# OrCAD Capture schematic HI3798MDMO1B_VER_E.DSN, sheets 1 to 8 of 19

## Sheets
1 SHEET01
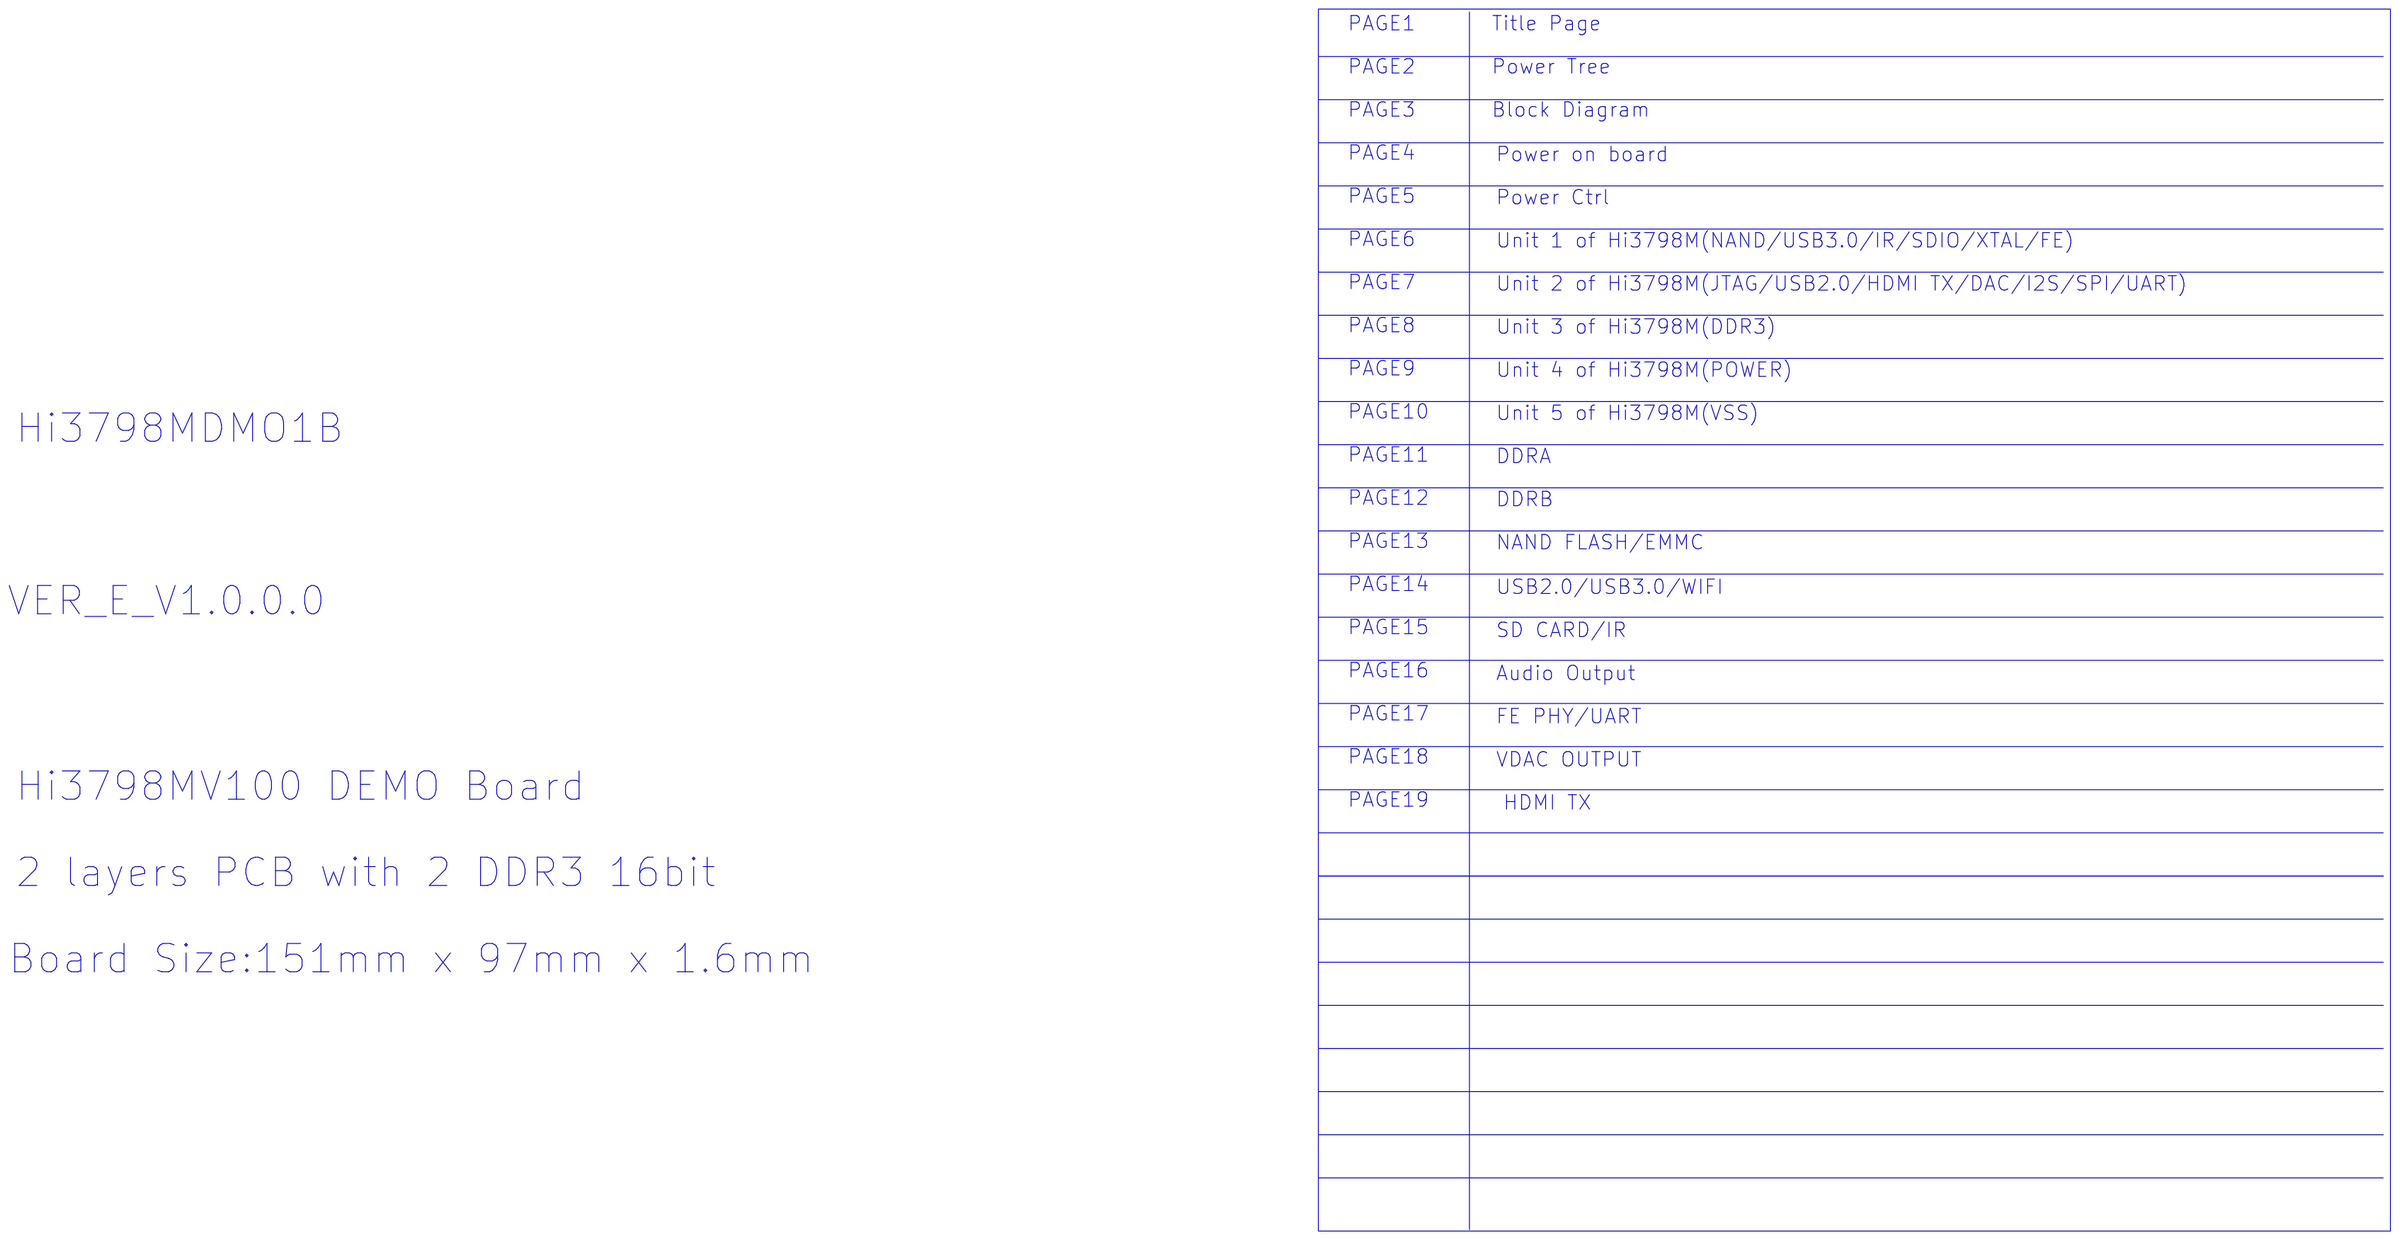
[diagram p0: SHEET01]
2 SHEET02
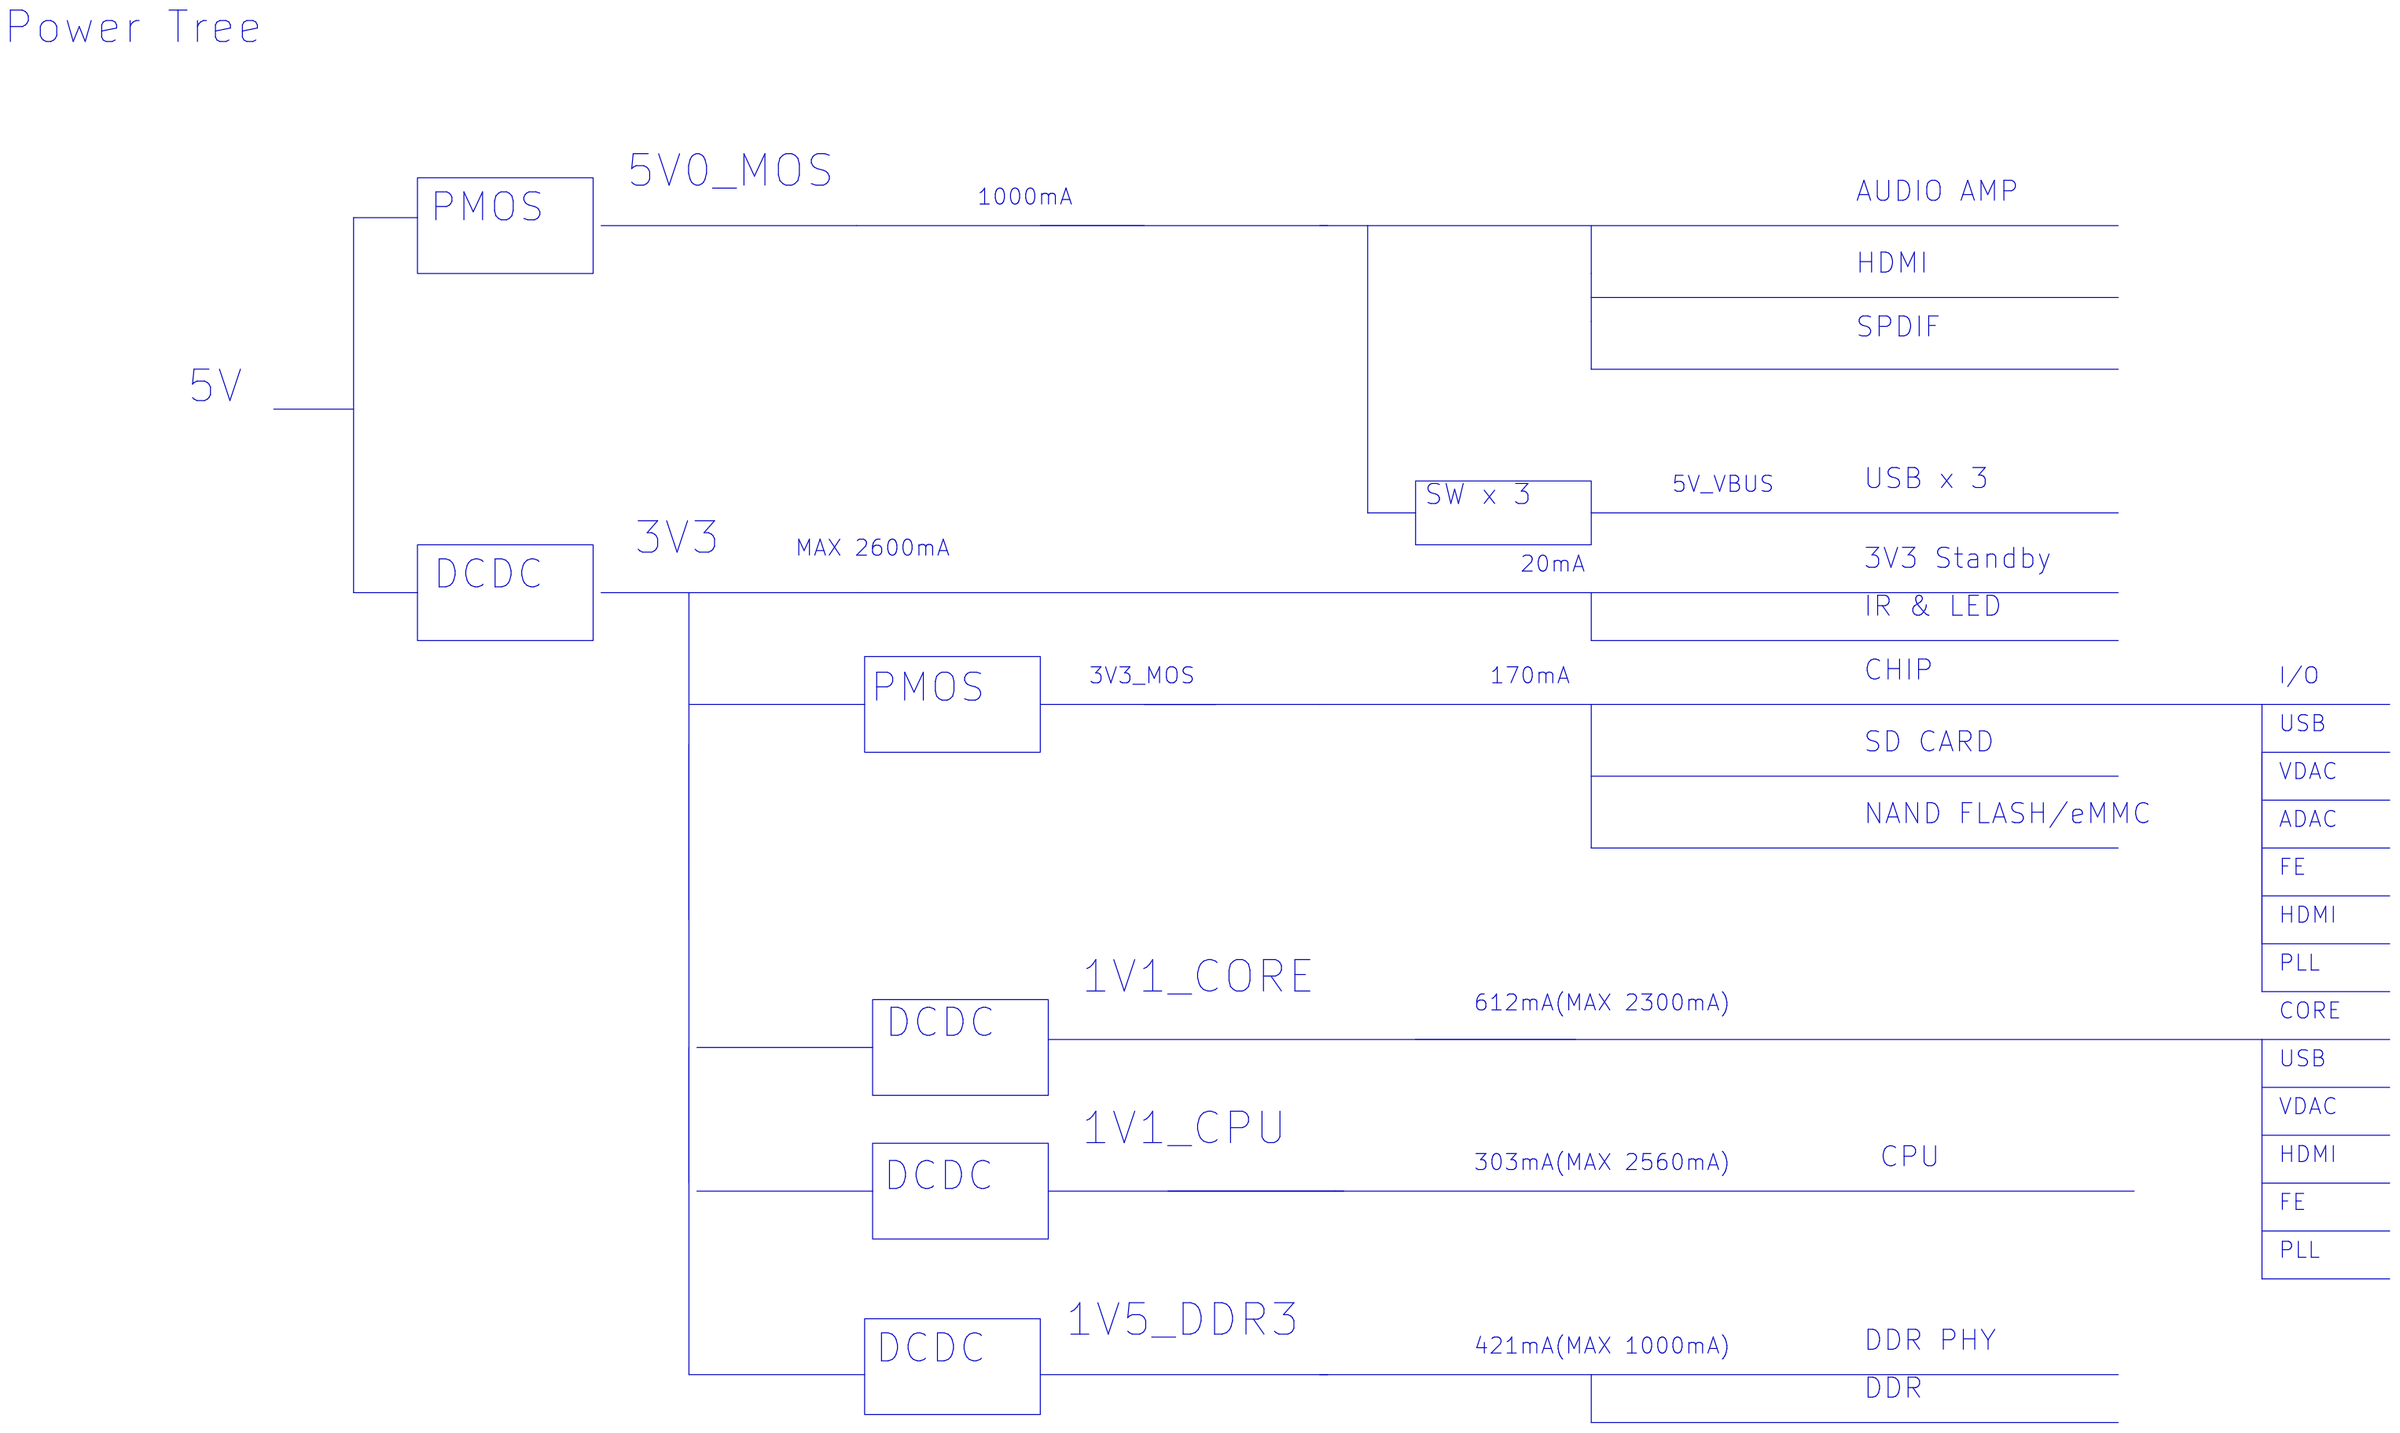
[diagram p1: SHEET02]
3 SHEET03: size Custom
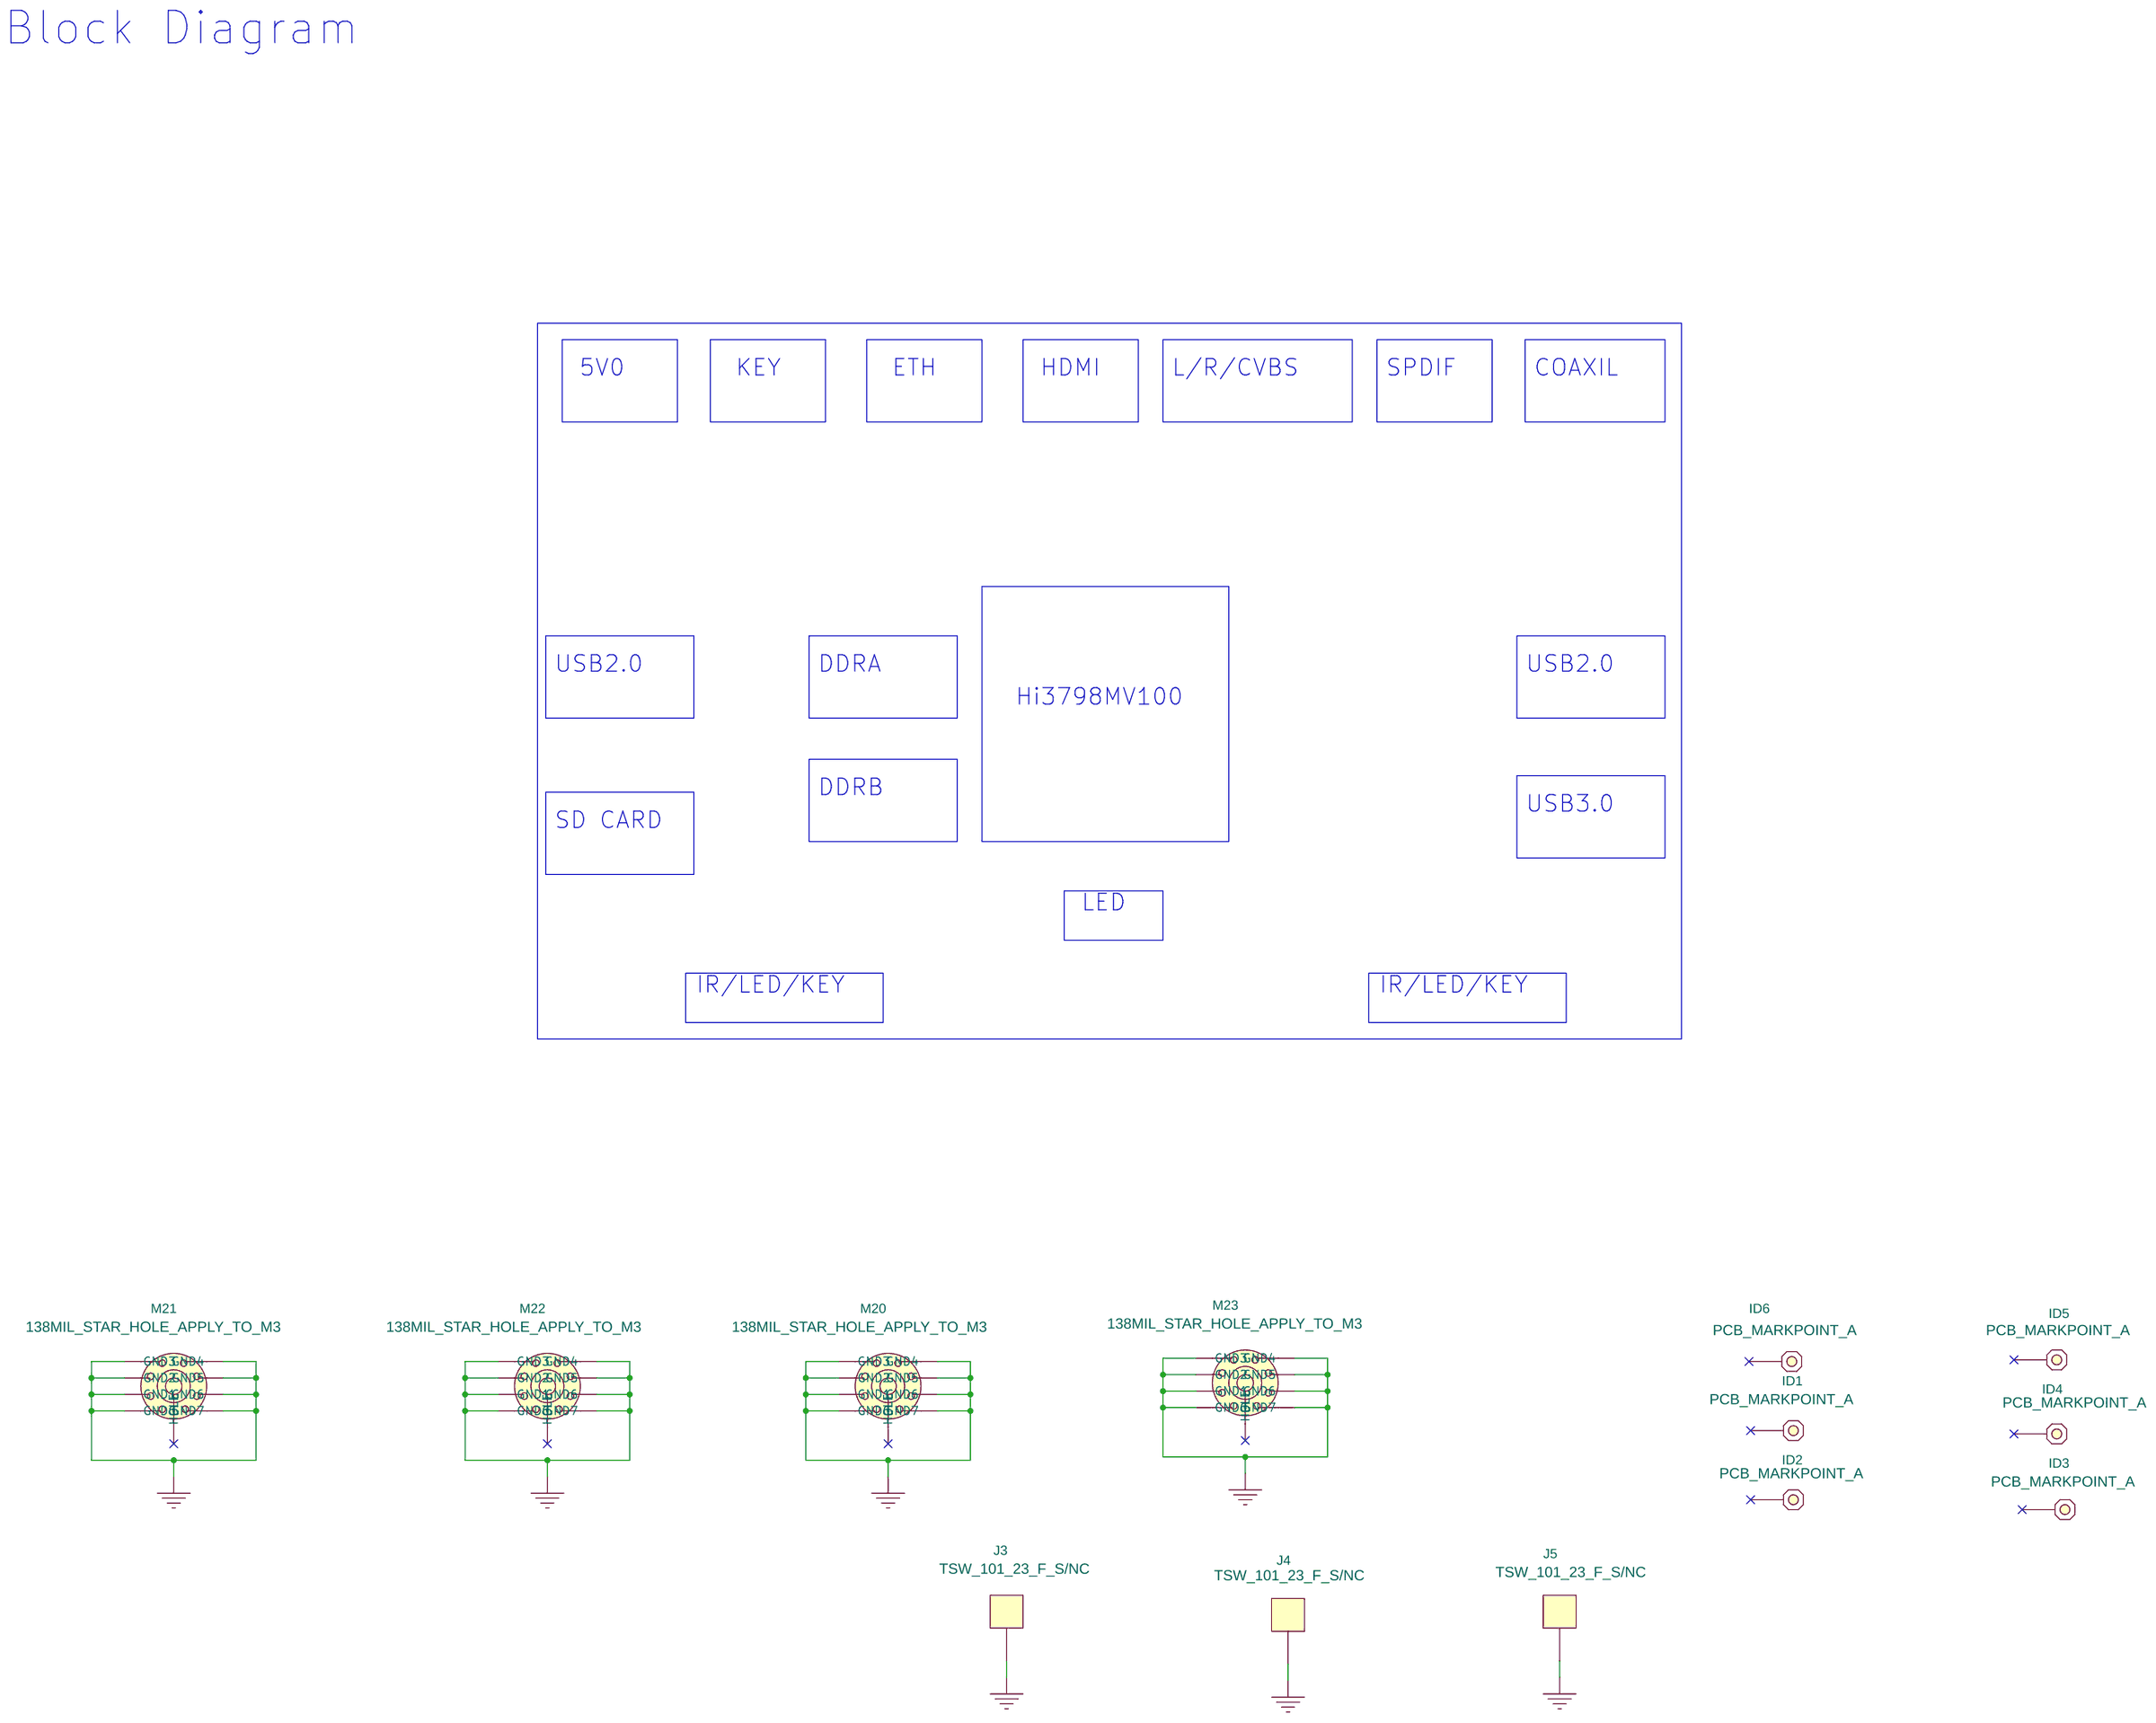
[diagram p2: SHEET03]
4 SHEET04: size Custom
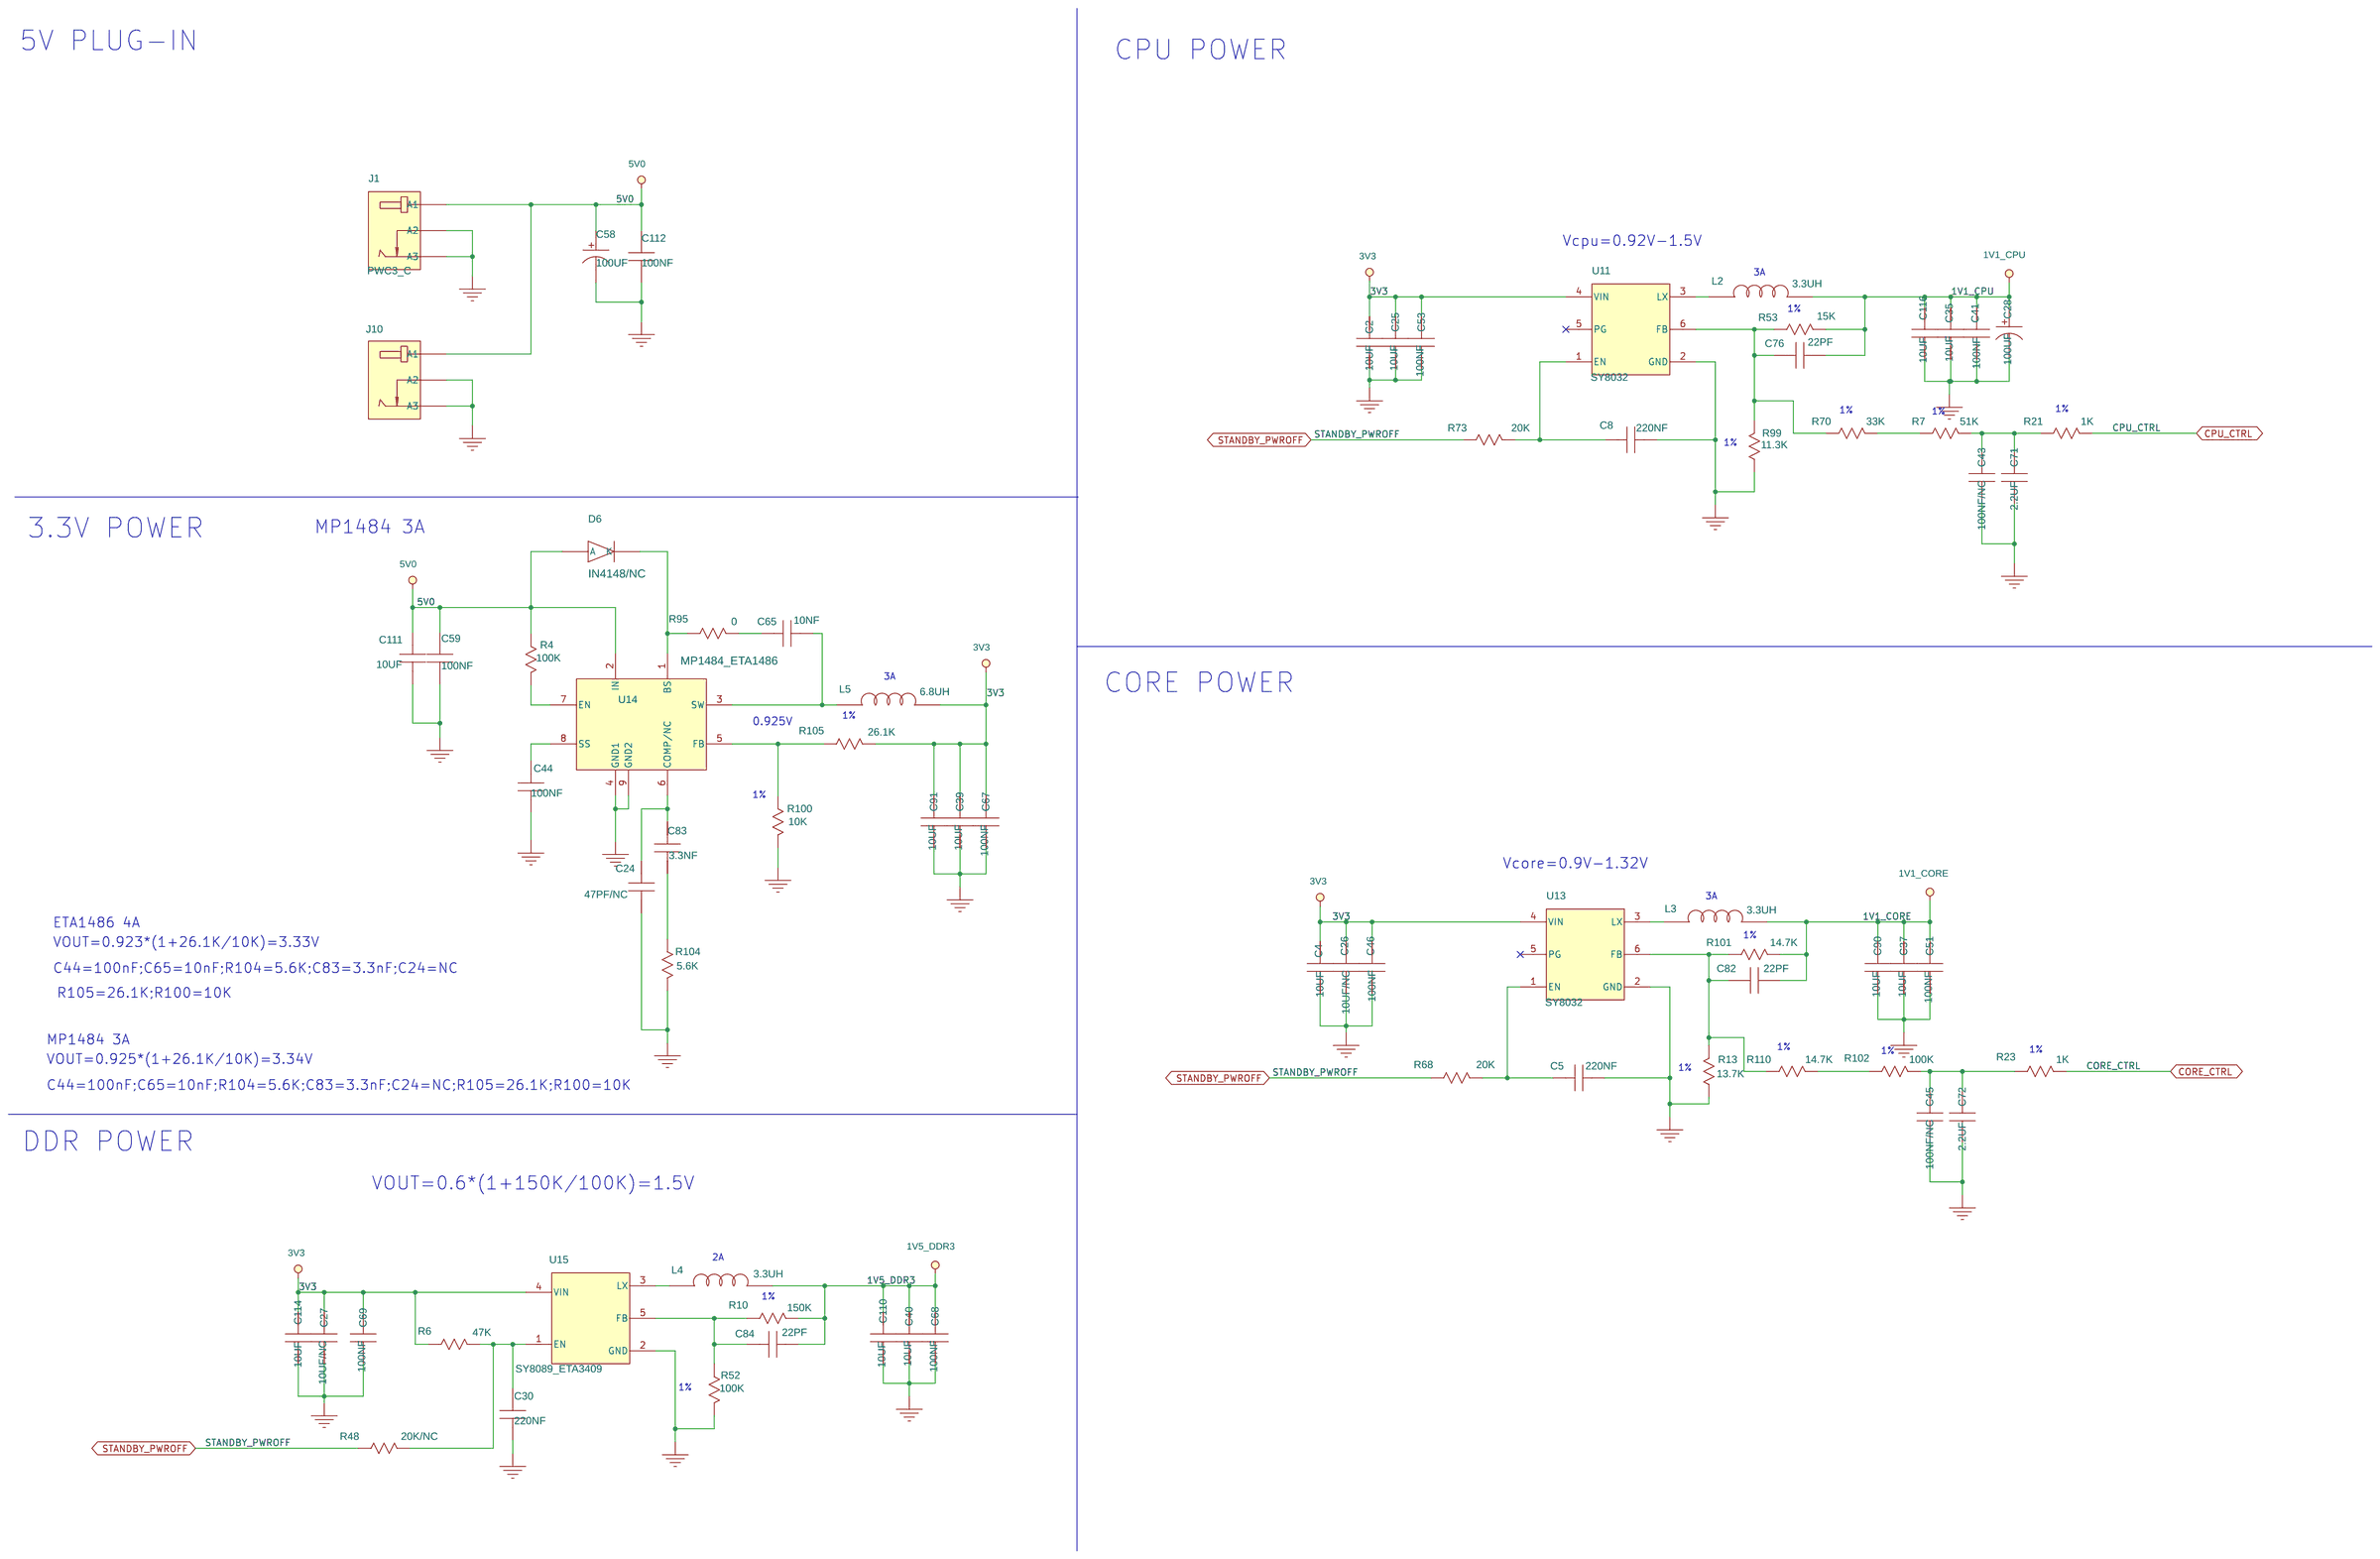
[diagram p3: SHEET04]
5 SHEET05: size A
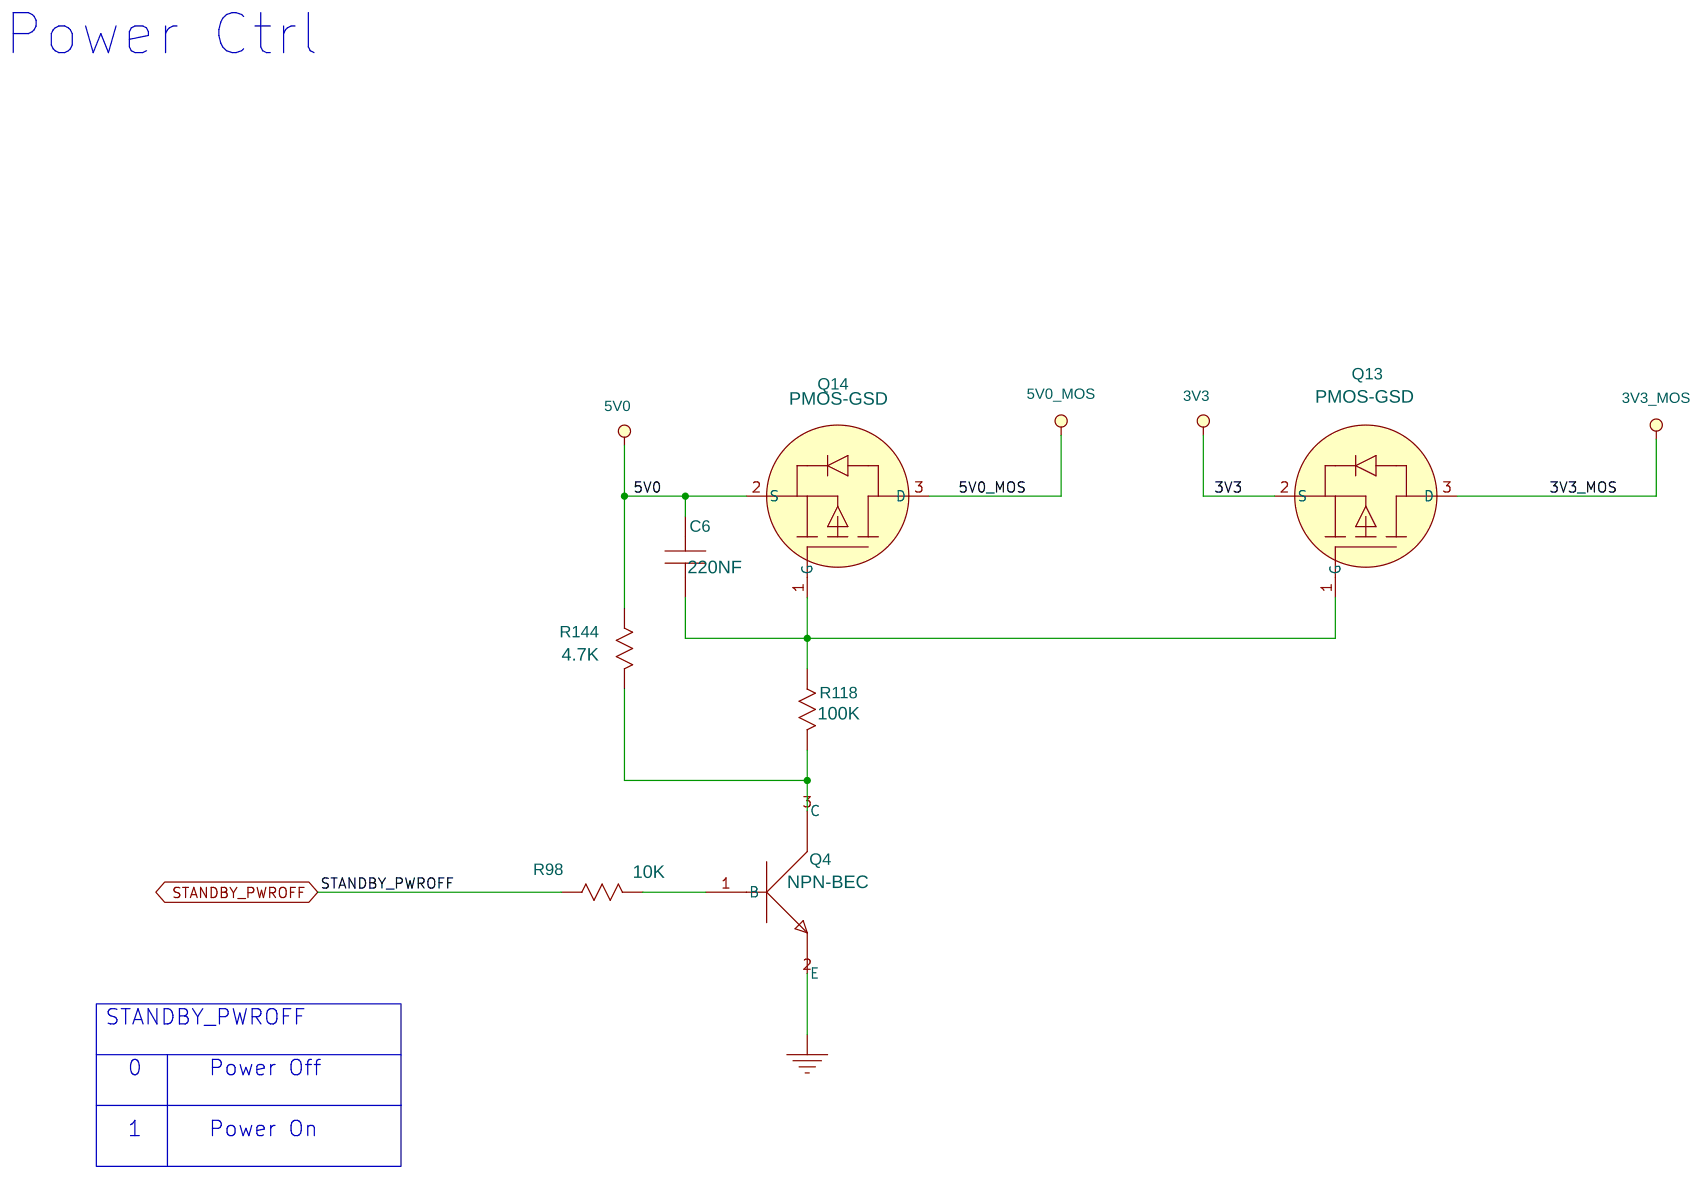
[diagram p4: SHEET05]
6 SHEET06: size Custom
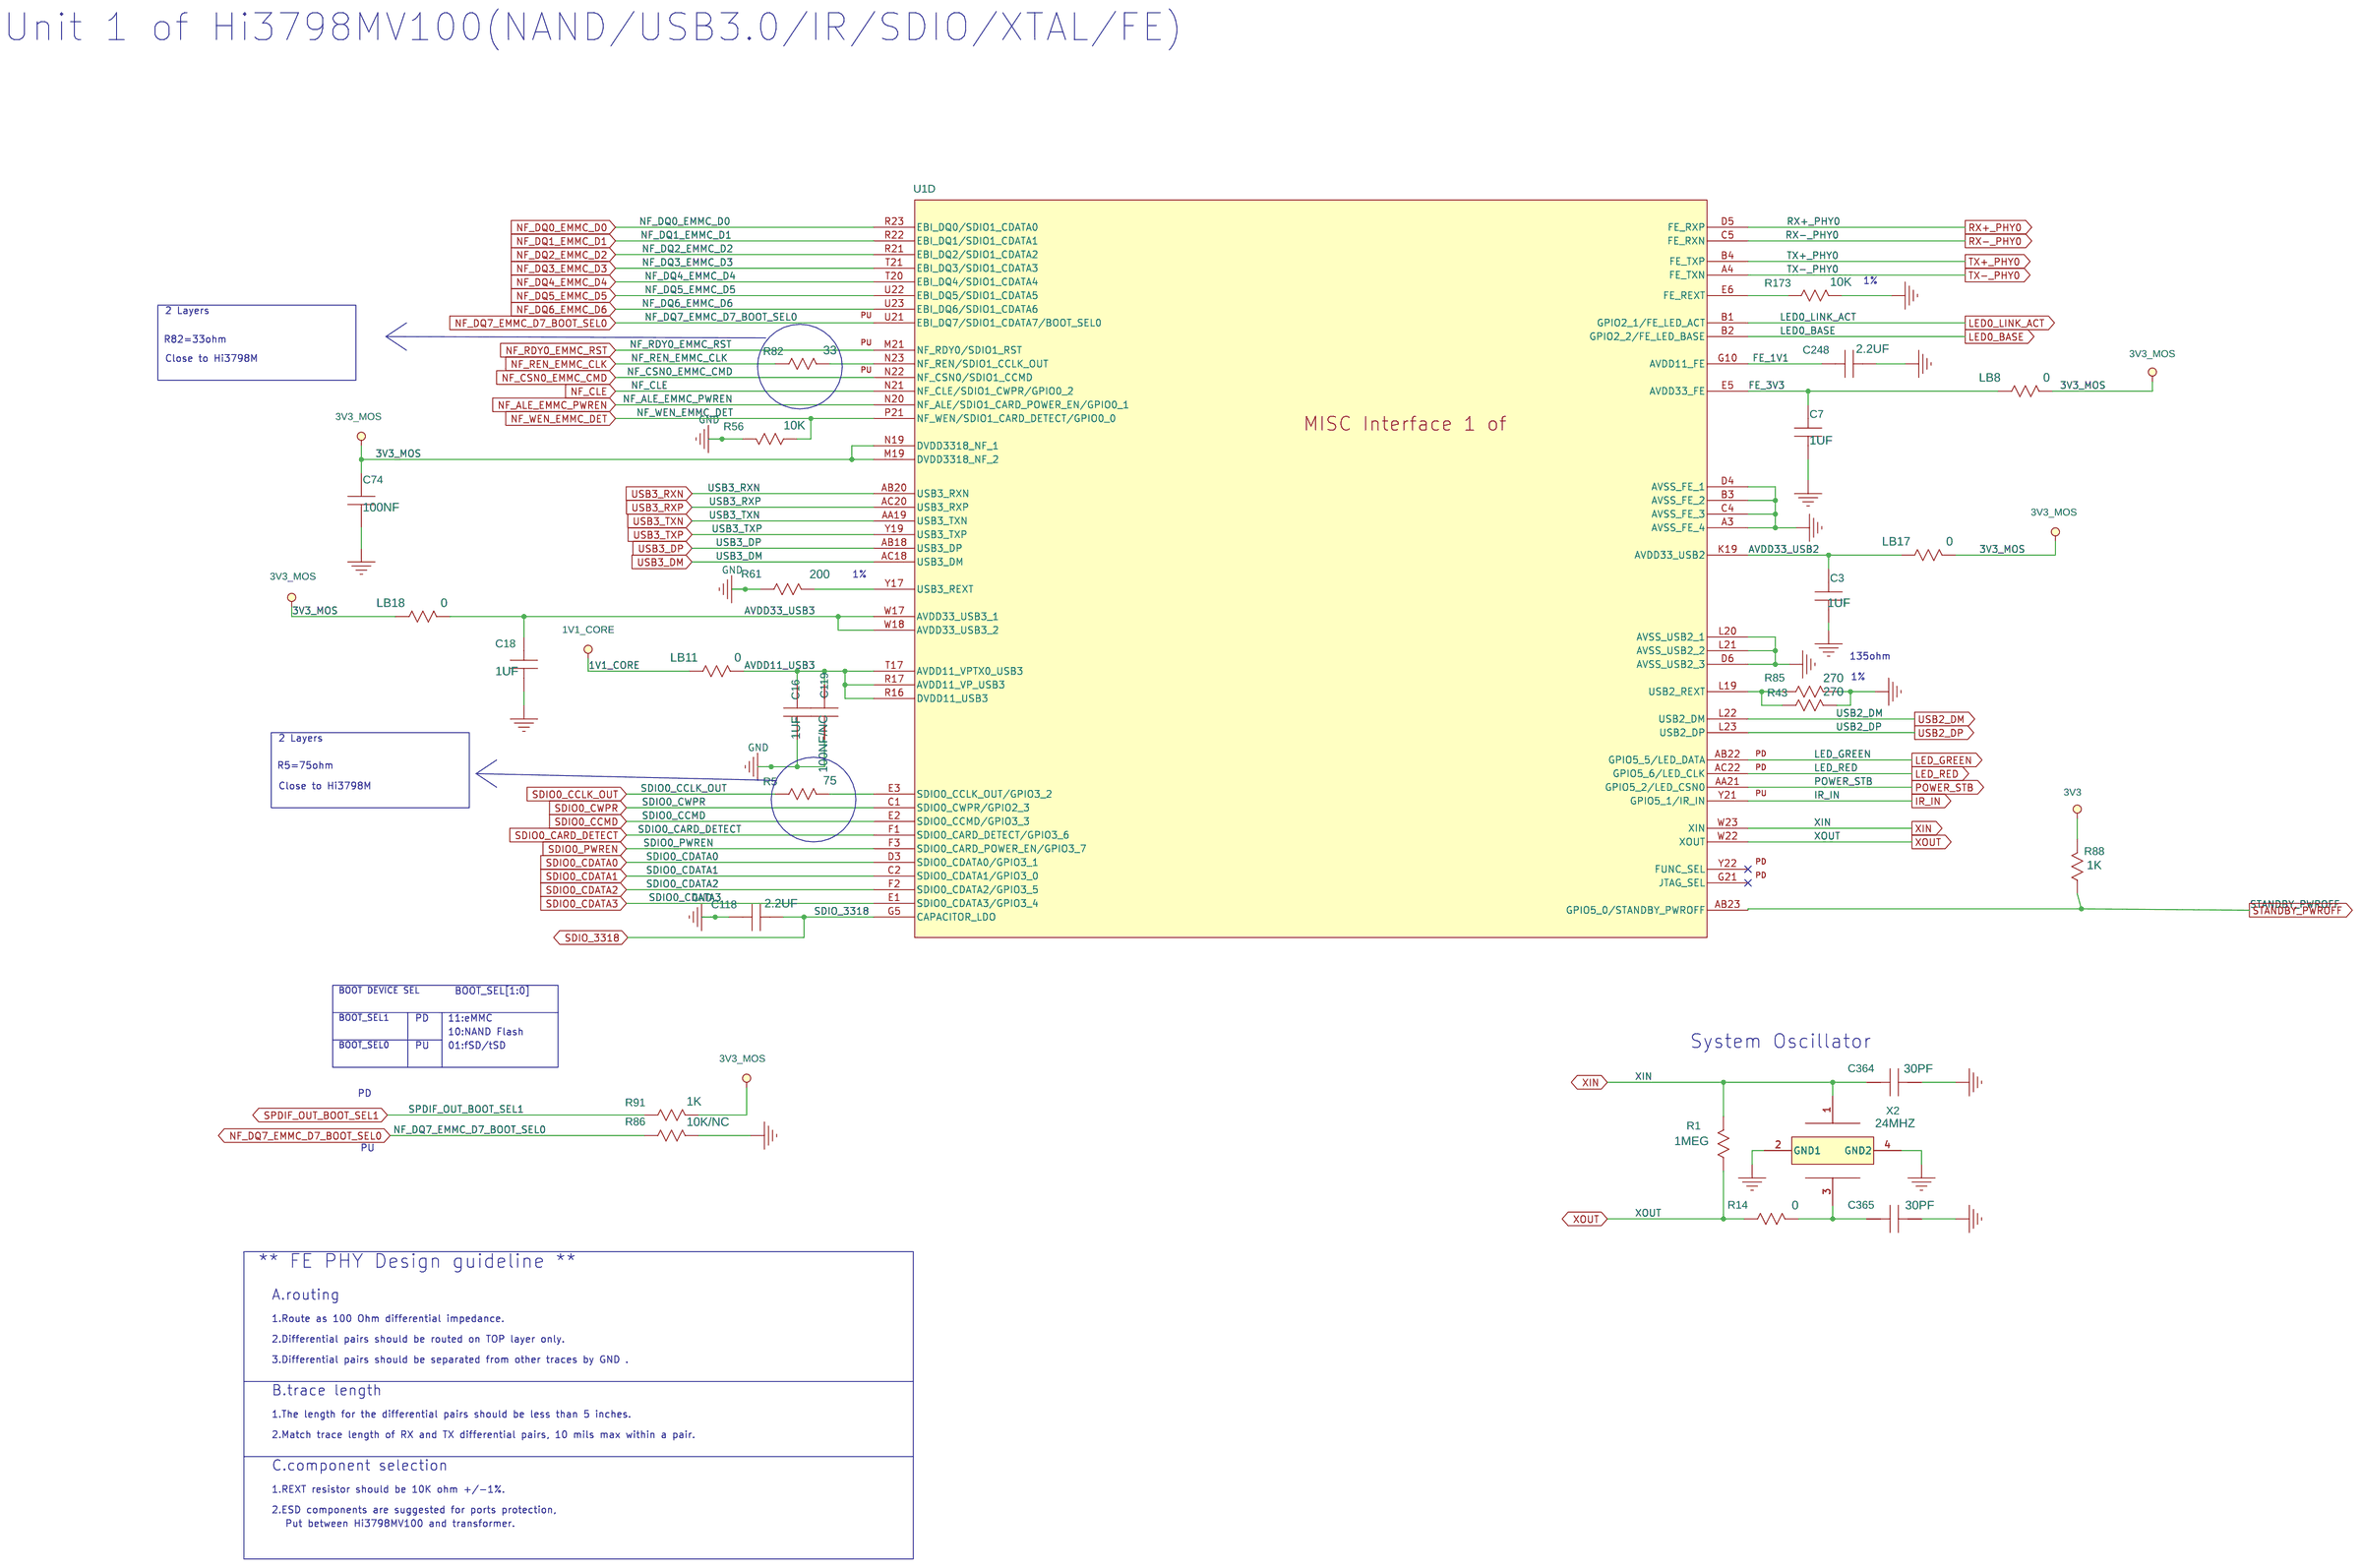
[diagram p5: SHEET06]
7 SHEET07: size Custom
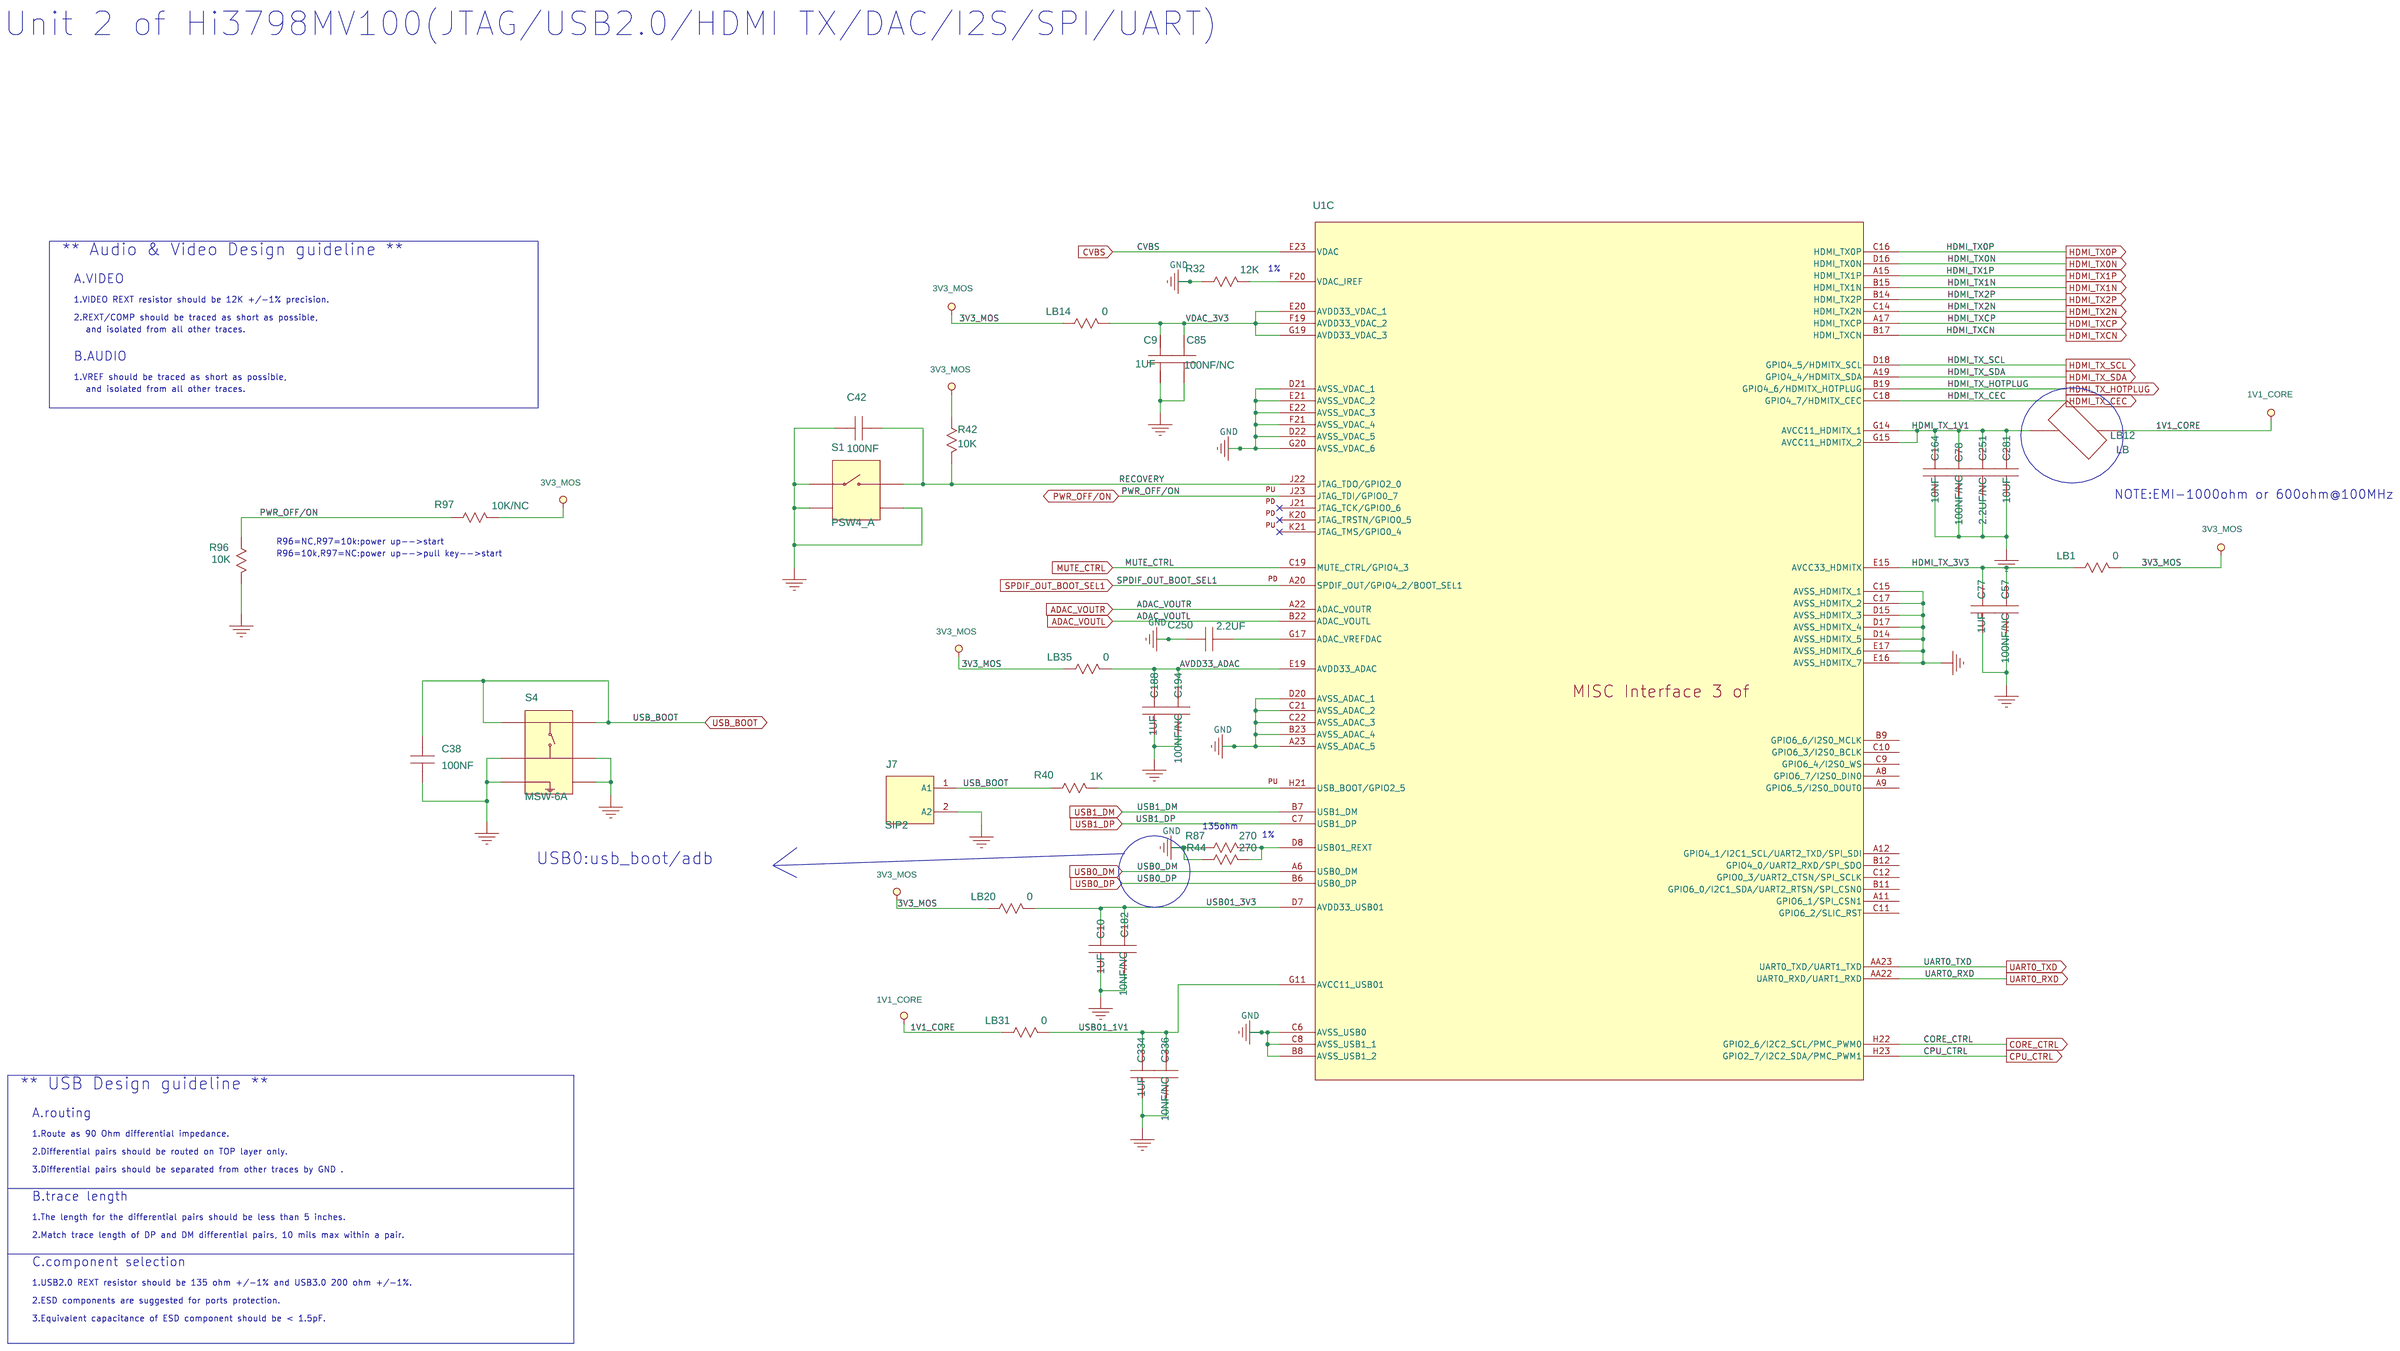
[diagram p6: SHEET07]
8 SHEET08: size Custom
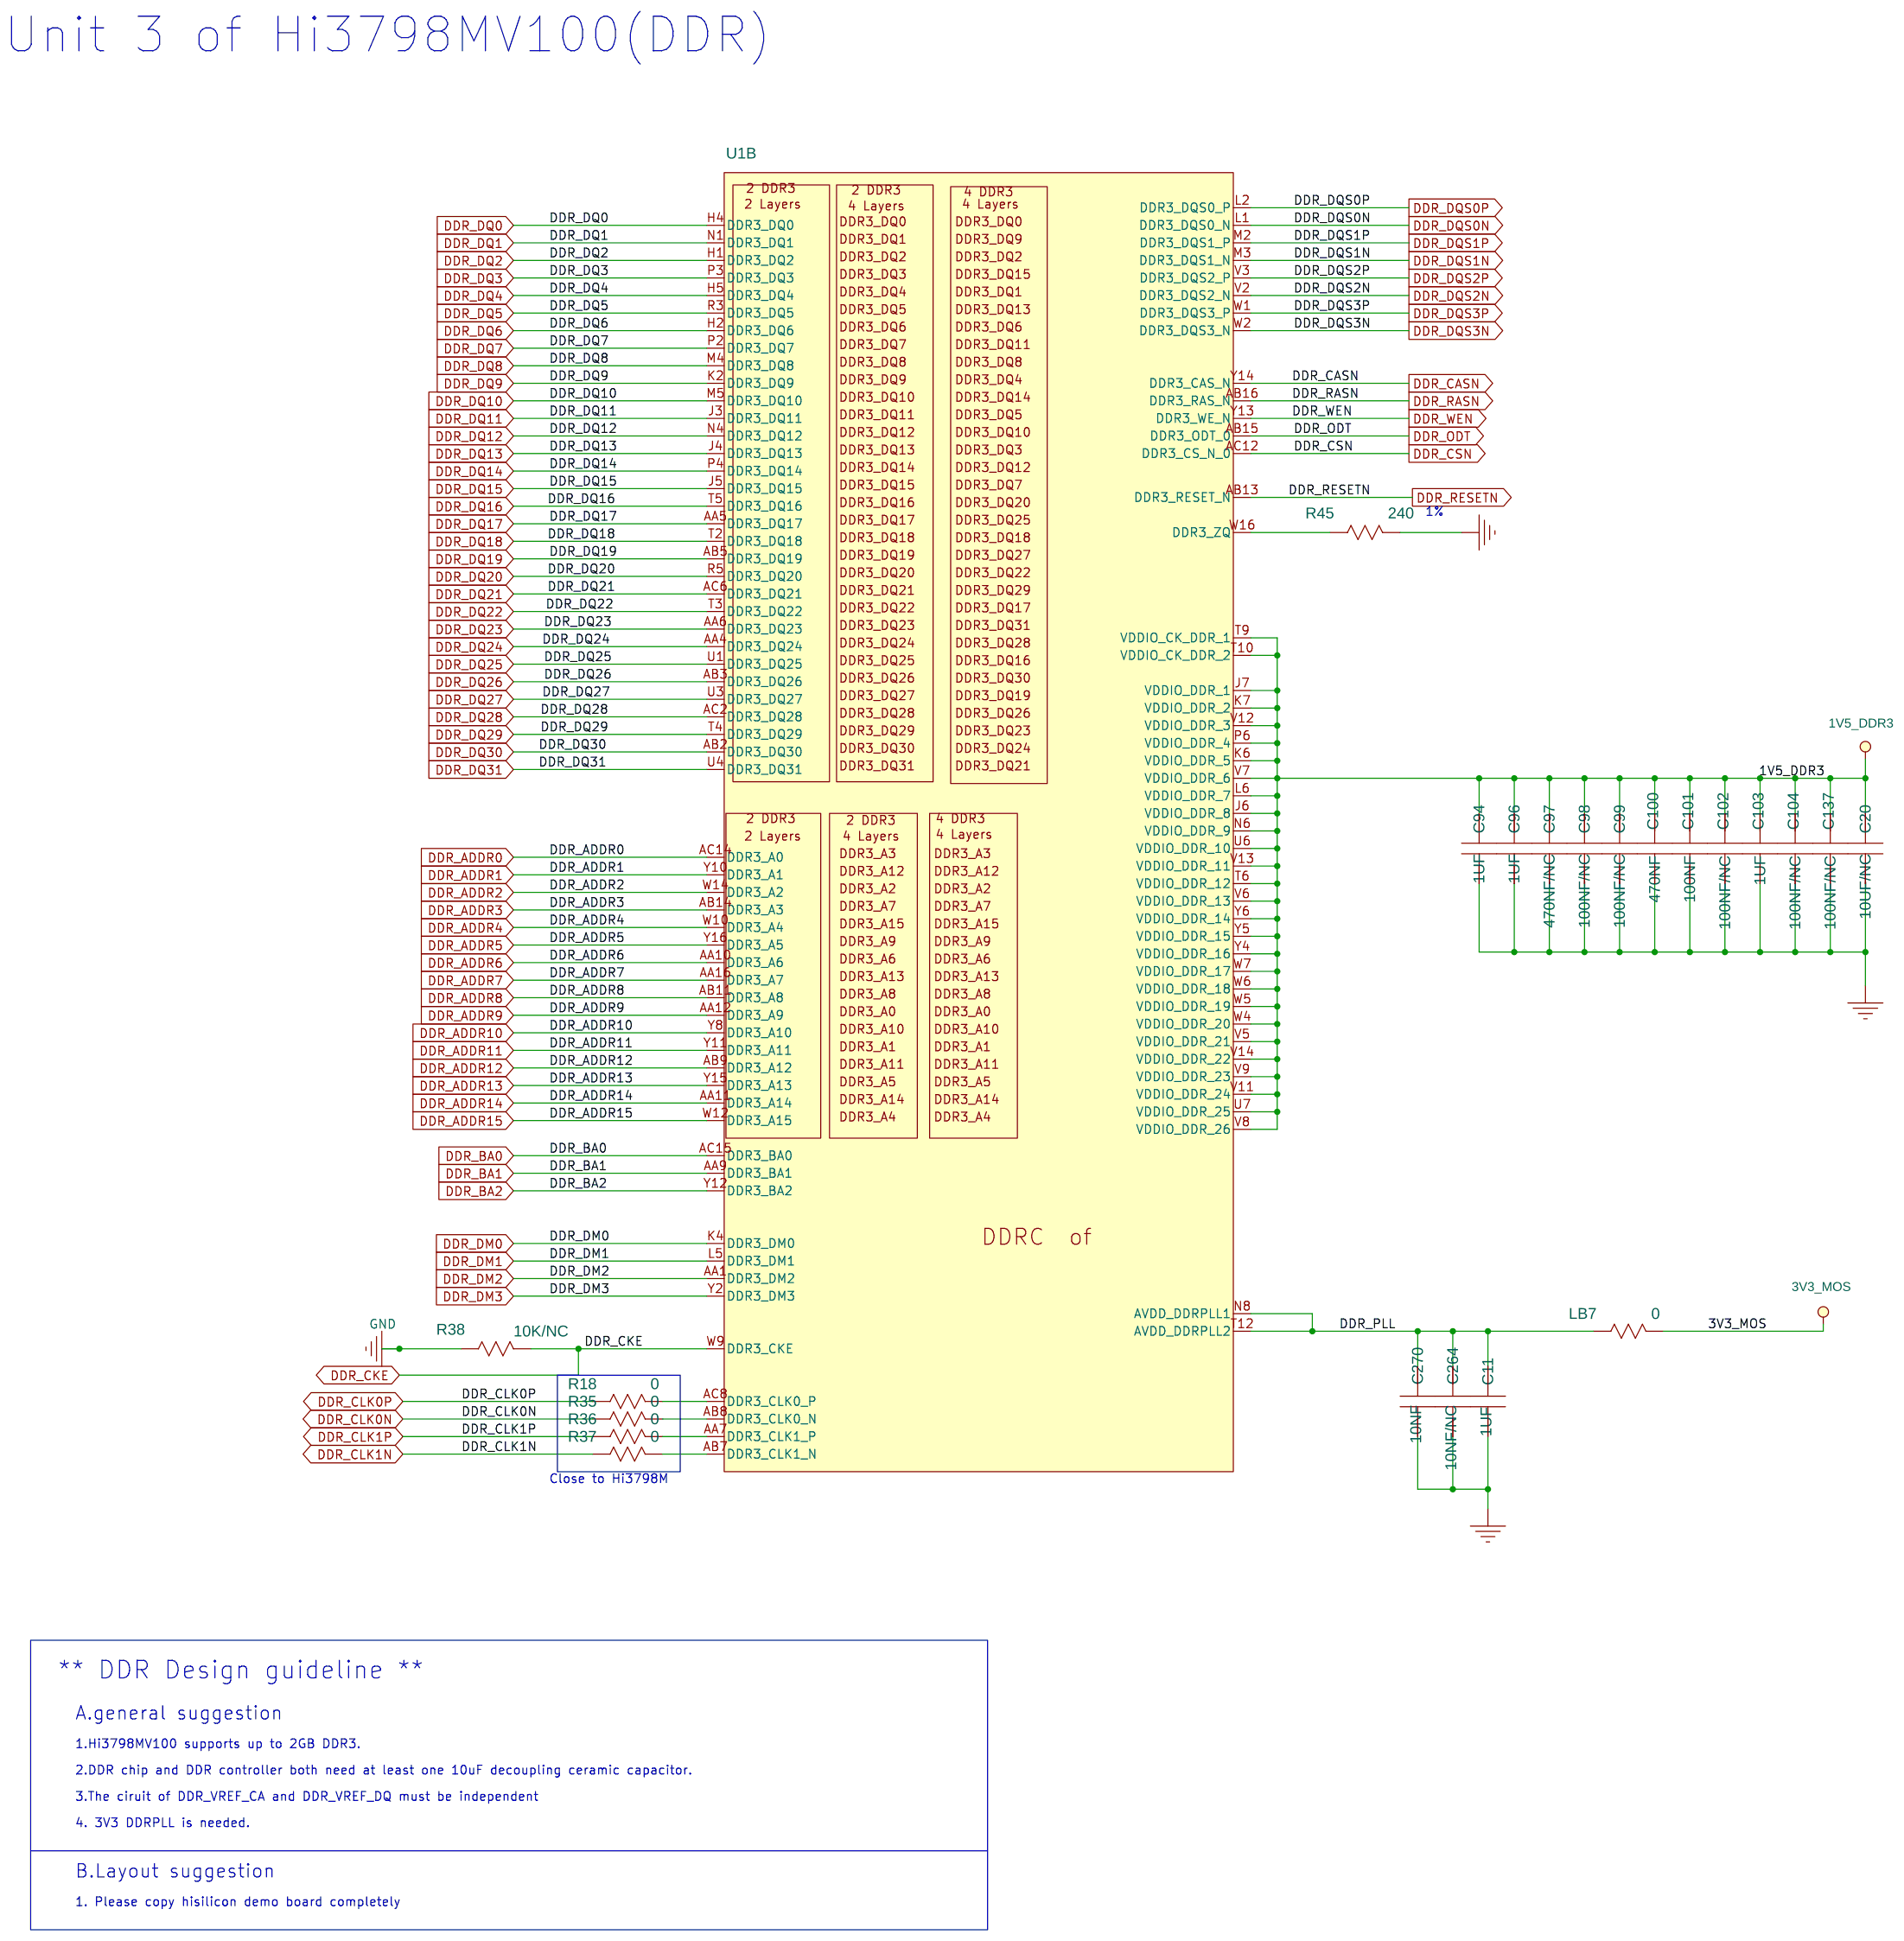
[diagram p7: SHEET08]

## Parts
sheet SHEET03
ID1  ID-BOARD  [ID-BOARD]
ID2  ID-BOARD  [ID-BOARD]
ID3  ID-BOARD  [ID-BOARD]
ID4  ID-BOARD  [ID-BOARD]
ID5  ID-BOARD  [ID-BOARD]
ID6  ID-BOARD  [ID-BOARD]
J3  SIP1  [SIP-1P]
J4  SIP1  [SIP-1P]
J5  SIP1  [SIP-1P]
M20  HOLE-8STARS  [HOLE138-8STAR]
M21  HOLE-8STARS  [HOLE138-8STAR]
M22  HOLE-8STARS  [HOLE138-8STAR]
M23  HOLE-8STARS  [HOLE138-8STAR]
sheet SHEET04
C2  10UF  [SC0805]
C4  10UF  [SC0805]
C5  220NF  [SC0402]
C8  220NF  [SC0402]
C24  47PF/NC  [SC0402]
C25  10UF  [SC0805]
C26  10UF/NC  [SC0805]
C27  10UF/NC  [SC0805]
C28  100UF  [SAC6666]
C30  220NF  [SC0402]
C35  10UF  [SC0603]
C37  10UF  [SC0603]
C39  10UF  [SC0603]
C40  10UF  [SC0603]
C41  100NF  [SC0402]
C43  100NF/NC  [SC0402]
C44  100NF  [SC0402]
C45  100NF/NC  [SC0402]
C46  100NF  [SC0402]
C51  100NF  [SC0402]
C53  100NF  [SC0402]
C58  100UF  [SAC6666]
C59  100NF  [SC0402]
C65  10NF  [SC0402]
C67  100NF  [SC0402]
C68  100NF  [SC0402]
C69  100NF  [SC0402]
C71  2.2UF  [SC0603]
C72  2.2UF  [SC0603]
C76  22PF  [SC0402]
C82  22PF  [SC0402]
C83  3.3NF  [SC0402]
C84  22PF  [SC0402]
C90  10UF  [SC0603]
C91  10UF  [SC0603]
C110  10UF  [SC0603]
C111  10UF  [SC0805]
C112  100NF  [SC0402]
C114  10UF  [SC0805]
C116  10UF  [SC0603]
D6  IN4148/NC  [HSOD323A]
J1  PWC3_C  [PWC3-RF-A]
J10  NC  [DC-002]
L2  3.3UH  [SWPA4020S]
L3  3.3UH  [SWPA4020S]
L4  3.3UH  [SWPA4020S]
L5  6.8UH  [SWPA5040S]
R4  100K  [SR0402]
R6  47K  [SR0402]
R7  51K  [SR0402]
R10  150K  [SR0402]
R13  13.7K  [SR0402]
R21  1K  [SR0402]
R23  1K  [SR0402]
R48  20K/NC  [SR0402]
R52  100K  [SR0402]
R53  15K  [SR0402]
R68  20K  [SR0402]
R70  33K  [SR0402]
R73  20K  [SR0402]
R95  0  [SR0402]
R99  11.3K  [SR0402]
R100  10K  [SR0402]
R101  14.7K  [SR0402]
R102  100K  [SR0402]
R104  5.6K  [SR0402]
R105  26.1K  [SR0402]
R110  14.7K  [SR0402]
U11  SY8032  [SOT23_6]
U13  SY8032  [SOT23_6]
U14  MP1484_ETA1486  [SOIC8N]
U15  SY8089_ETA3409  [SOT23_5]
sheet SHEET05
C6  220NF  [SC0603]
Q4  NPN-BEC  [SOT23]
Q13  PMOS-GSD  [SOT23]
Q14  PMOS-GSD  [SOT23]
R98  10K  [SR0402]
R118  100K  [SR0402]
R144  4.7K  [SR0402]
sheet SHEET06
C3  1UF  [SC0603]
C7  1UF  [SC0603]
C16  1UF  [SC0603]
C18  1UF  [SC0603]
C74  100NF  [SC0402]
C118  2.2UF  [HSC0402]
C119  100NF/NC  [SC0402]
C248  2.2UF  [HSC0402]
C364  30PF  [SC0402]
C365  30PF  [SC0402]
LB8  0  [SL0402]
LB11  0  [SL0402]
LB17  0  [SL0603]
LB18  0  [SL0402]
R1  1MEG  [SR0603]
R5  75  [SR0402]
R14  0  [SR0402]
R43  270  [SR0402]
R56  10K  [SR0402]
R61  200  [SR0402]
R82  33  [SR0402]
R85  270  [SR0402]
R86  10K/NC  [SR0402]
R88  1K  [SR0402]
R91  1K  [SR0402]
R173  10K  [SR0402]
X2  24MHZ  [X288]
sheet SHEET07
C9  1UF  [SC0603]
C10  1UF  [SC0603]
C38  100NF  [SC0402]
C42  100NF  [SC0402]
C57  100NF/NC  [SC0402]
C77  1UF  [SC0402]
C78  100NF/NC  [SC0402]
C85  100NF/NC  [SC0402]
C164  10NF  [SC0402]
C182  10NF/NC  [SC0402]
C188  1UF  [SC0603]
C194  100NF/NC  [SC0402]
C250  2.2UF  [HSC0402]
C251  2.2UF/NC  [SC0603]
C281  10UF  [SC0603]
C334  1UF  [SC0402]
C336  10NF/NC  [SC0402]
J7  SIP2  [SIP-2P]
LB1  0  [SL0402]
LB12  LB  [SL0402]
LB14  0  [SL0603]
LB20  0  [SL0402]
LB31  0  [SL0402]
LB35  0  [SL0402]
R32  12K  [SR0402]
R40  1K  [SR0402]
R42  10K  [SR0402]
R44  270  [SR0402]
R87  270  [SR0402]
R96  10K  [SR0402]
R97  10K/NC  [SR0402]
S1  PSW4_A  [TSW4-RG-C]
S4  MSW-6A  [SPSW6-T]
sheet SHEET08
C11  1UF  [SC0603]
C20  10UF/NC  [SC0805]
C94  1UF  [SC0402]
C96  1UF  [SC0402]
C97  470NF/NC  [SC0402]
C98  100NF/NC  [SC0402]
C99  100NF/NC  [SC0402]
C100  470NF  [SC0402]
C101  100NF  [SC0402]
C102  100NF/NC  [SC0402]
C103  1UF  [SC0402]
C104  100NF/NC  [SC0402]
C137  100NF/NC  [SC0402]
C264  10NF/NC  [SC0402]
C270  10NF  [SC0402]
LB7  0  [SL0603]
R18  0  [SR0402]
R35  0  [SR0402]
R36  0  [SR0402]
R37  0  [SR0402]
R38  10K/NC  [SR0402]
R45  240  [SR0402]
sheet SHEET09
U1  S40V300_19X19  [TFBGA395-32-2323]  (sections A,B,C,D,E)

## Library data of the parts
ID1-ID6 = ID-BOARD: %195%%232%%202%%246%: PCB-MARK点ID-BOARD，亮铜直径40MIL，阻焊开窗直径80MIL，MARK点大小120MIL。; DEVICE: PCB_MARKPOINT_A
J3-J5 = SIP1: %195%%232%%202%%246%: 插针-普通方脚插针-1PIN-单排-直式-5.84MM-2.92MM-2.54MM-THT; %208%%161%%192%%224%%195%%251%%179%%198%: 插针; CODE: 14050101; DEVICE: TSW_101_23_F_S/NC
M20-M23 = HOLE-8STARS: %195%%232%%202%%246%: M3螺钉(推荐使用)，对应138MIL星月孔，适用于过波峰焊设计。; DEVICE: 138MIL_STAR_HOLE_APPLY_TO_M3
C2 C4 C25-C27 C111 C114 = C: %182%%238%%182%%168%%185%%164%%215%%247%%181%%231%%209%%185%(V): 25; %195%%232%%202%%246%: SMD陶瓷电容-25V-10000NF-+/-20%-X5R-0805; %208%%161%%192%%224%%195%%251%%179%%198%: SMD陶瓷电容; CODE: 8071629; COMPONENT_HIGH_MAX: 1.45MM; DEVICE: C2012X5R1E106KT000N1
C5 C8 C30 = C: %182%%238%%182%%168%%185%%164%%215%%247%%181%%231%%209%%185%(V): 6.3; %195%%232%%202%%246%: SMD陶瓷电容-6.3V-220NF-+/-10%-X5R-0402-BT; %208%%161%%192%%224%%195%%251%%179%%198%: SMD陶瓷电容; CODE: 8070584; COMPONENT_HIGH_MAX: 0.55MM; DEVICE: GRM155R60J224KE01D
C24 = C: %182%%238%%182%%168%%185%%164%%215%%247%%181%%231%%209%%185%(V): 50; %195%%232%%202%%246%: SMD陶瓷电容-50V-0.047NF-±5%-NP0-0402; %208%%161%%192%%224%%195%%251%%179%%198%: SMD陶瓷电容; CODE: 8070549; COMPONENT_HIGH_MAX: 0.55MM; DEVICE: C0402C470J5GAC_7867
C28 C58 = CP: %182%%238%%182%%168%%185%%164%%215%%247%%181%%231%%209%%185%(V): 16; %195%%232%%202%%246%: 非固体SMD铝电容-16V-100UF-+/-20%-6.3*5.4MM-极性-105DEGC-1000H-片式,温度敏感器件-工艺耐温250DEGC,5S; %208%%161%%192%%224%%195%%251%%179%%198%: 非固体SMD铝电容; CODE: 8010269; COMPONENT_HIGH_MAX: 5.7MM; DEVICE: UWT1C101MCL1GB
C35 C37 C39 C40 C90 C91 C110 C116 C281 = C: %182%%238%%182%%168%%185%%164%%215%%247%%181%%231%%209%%185%(V): 6.3; %195%%232%%202%%246%: SMD陶瓷电容-6.3V-10000NF-+/-20%-X5R-0603-BT,TS16949; %208%%161%%192%%224%%195%%251%%179%%198%: SMD陶瓷电容; CODE: 8070649; COMPONENT_HIGH_MAX: 0.9MM; DEVICE: C1608X5R0J106MT0A0E
C41 C43 C45 C46 C51 C53 C59 C67-C69 C112 = C: %182%%238%%182%%168%%185%%164%%215%%247%%181%%231%%209%%185%(V): 16; %195%%232%%202%%246%: SMD陶瓷电容-16V-100NF-±10%-X7R-0402; %208%%161%%192%%224%%195%%251%%179%%198%: SMD陶瓷电容; CODE: 8070614; COMPONENT_HIGH_MAX: 0.6MM; DEVICE: RMEMK105BJ104KV_FR
C44 = C: %182%%238%%182%%168%%185%%164%%215%%247%%181%%231%%209%%185%(V): 16; %195%%232%%202%%246%: SMD陶瓷电容-16V-10NF-+/-10%-X7R-0402; %208%%161%%192%%224%%195%%251%%179%%198%: SMD陶瓷电容; CODE: 8070449; COMPONENT_HIGH_MAX: 0.55MM; DEVICE: GRM155R71C103KA01D
C65 = C: %182%%238%%182%%168%%185%%164%%215%%247%%181%%231%%209%%185%(V): 10; %195%%232%%202%%246%: SMD陶瓷电容-10V-33NF-+/-10%-X7R-0402; %208%%161%%192%%224%%195%%251%%179%%198%: SMD陶瓷电容; CODE: 8070598; COMPONENT_HIGH_MAX: 0.55MM; DEVICE: C1005X7R1C333KT000F
C71 C72 C251 = C: %182%%238%%182%%168%%185%%164%%215%%247%%181%%231%%209%%185%(V): 10; %195%%232%%202%%246%: SMD陶瓷电容-10V-2200NF-+/-10%-X5R-0603; %208%%161%%192%%224%%195%%251%%179%%198%: SMD陶瓷电容; CODE: 8070573; COMPONENT_HIGH_MAX: 0.9MM; DEVICE: GRM188R61A225KE34D
C76 C82 C84 = C: %182%%238%%182%%168%%185%%164%%215%%247%%181%%231%%209%%185%(V): 50; %195%%232%%202%%246%: SMD陶瓷电容-50V-0.022NF-+/-5%-NP0-0402-BT; %208%%161%%192%%224%%195%%251%%179%%198%: SMD陶瓷电容; CODE: 8070545; COMPONENT_HIGH_MAX: 0.55MM; DEVICE: RMUMK105CG220JV_F
C83 = C: %182%%238%%182%%168%%185%%164%%215%%247%%181%%231%%209%%185%(V): 50; %195%%232%%202%%246%: SMD陶瓷电容-50V-3.3NF-±10%-X7R-0402; %208%%161%%192%%224%%195%%251%%179%%198%: SMD陶瓷电容; CODE: 8070621; COMPONENT_HIGH_MAX: 0.55MM; DEVICE: GRM155R71H332KA01D
D6 = D_A: %195%%232%%202%%246%: 肖特基二极管-10V-3A-0.24V-SOD323-BT; %208%%161%%192%%224%%195%%251%%179%%198%: 肖特基二极管; CODE: 15010252; COMPONENT_HIGH_MAX: 1.1MM; DEVICE: BAT60BE6327
J1 = PWC3_C: %195%%232%%202%%246%: IO连接器-DC JACK-3PIN-母座-3.9/1.3MM弯式-5V2A-00482858; CODE: 14240410; COMPONENT_HIGH_MAX: 11.25MM; DEVICE: DC_012_HW
J10 = PWC3_C: %195%%232%%202%%246%: IO连接器-DC JACK-3PIN-母座-3.9/1.3MM弯式-5V2A-00482858; CODE: *; COMPONENT_HIGH_MAX: 11.25MM; DEVICE: DC_012_HW
L2-L4 = SWPA4020S3R3MT
L5 = SWPA5040S6R8MT
R4 = R: %182%%238%%182%%168%%185%%166%%194%%202%(W): 0.06; %195%%232%%202%%246%: 片式厚膜电阻器-0.0625W-100000OHM-+/-5%-0402; %208%%161%%192%%224%%195%%251%%179%%198%: 片式厚膜电阻器; %215%%232%%214%%181%%212%%202%%208%%237%%198%%171%%178%%238%: +/-5%; CODE: 7090831; COMPONENT_HIGH_MAX: 0.4MM; DEVICE: RK73B1ELTP104J
R6 = R: %182%%238%%182%%168%%185%%166%%194%%202%(W): 0.06; %195%%232%%202%%246%: 片式厚膜电阻器-0.0625W-47000OHM-+/-5%-0402-ELOM; %208%%161%%192%%224%%195%%251%%179%%198%: 片式厚膜电阻器; %215%%232%%214%%181%%212%%202%%208%%237%%198%%171%%178%%238%: +/-5%; CODE: 7090819; COMPONENT_HIGH_MAX: 0.4MM; DEVICE: RC0402JR_0747K
R7 R105 = R: %182%%238%%182%%168%%185%%166%%194%%202%(W): 0.06; %195%%232%%202%%246%: 片式厚膜电阻器-0.0625W-51000OHM-+/-1%-0402; %208%%161%%192%%224%%195%%251%%179%%198%: 片式厚膜电阻器; %215%%232%%214%%181%%212%%202%%208%%237%%198%%171%%178%%238%: +/-1%; CODE: 7091384; COMPONENT_HIGH_MAX: 0.4MM; DEVICE: RC_02W5102FT
R10 = R: %182%%238%%182%%168%%185%%166%%194%%202%(W): 0.06; %195%%232%%202%%246%: 片式厚膜电阻器-0.0625W-150000OHM-+/-1%-0402; %208%%161%%192%%224%%195%%251%%179%%198%: 片式厚膜电阻器; %215%%232%%214%%181%%212%%202%%208%%237%%198%%171%%178%%238%: +/-1%; CODE: 7090833; COMPONENT_HIGH_MAX: 0.4MM; DEVICE: RK73H1ELTP1503F
R13 = R: %182%%238%%182%%168%%185%%166%%194%%202%(W): 0.1; %195%%232%%202%%246%: 片式厚膜电阻器-0.1W-26100OHM-+/-1%-0603-BT; %208%%161%%192%%224%%195%%251%%179%%198%: 片式厚膜电阻器; %215%%232%%214%%181%%212%%202%%208%%237%%198%%171%%178%%238%: +/-1%; CODE: 7091991; COMPONENT_HIGH_MAX: 0.55MM; DEVICE: RK73H1JTTD2612F
R21 R23 = R: %182%%238%%182%%168%%185%%166%%194%%202%(W): 0.1; %195%%232%%202%%246%: 片式厚膜电阻器-0.1W-1000OHM-+/-1%-0603; %208%%161%%192%%224%%195%%251%%179%%198%: 片式厚膜电阻器; %215%%232%%214%%181%%212%%202%%208%%237%%198%%171%%178%%238%: +/-1%; CODE: 7092250; COMPONENT_HIGH_MAX: 0.5MM; DEVICE: RK73H1JTTD1001F
R48 R68 R73 = R: %182%%238%%182%%168%%185%%166%%194%%202%(W): 0.06; %195%%232%%202%%246%: 片式厚膜电阻器-0.0625W-20000OHM-+/-1%-0402-TS16949; %208%%161%%192%%224%%195%%251%%179%%198%: 片式厚膜电阻器; %215%%232%%214%%181%%212%%202%%208%%237%%198%%171%%178%%238%: +/-1%; CODE: 7091374; COMPONENT_HIGH_MAX: 0.65MM; DEVICE: RC_02W2002FT
R52 R118 = R: %182%%238%%182%%168%%185%%166%%194%%202%(W): 0.06; %195%%232%%202%%246%: 片式厚膜电阻器-0.0625W-100000OHM-+/-5%-0402-BT; %208%%161%%192%%224%%195%%251%%179%%198%: 片式厚膜电阻器; %215%%232%%214%%181%%212%%202%%208%%237%%198%%171%%178%%238%: +/-5%; CODE: 7090831; COMPONENT_HIGH_MAX: 0.4MM; DEVICE: RK73B1ELTP104J
R53 R100 = R: %182%%238%%182%%168%%185%%166%%194%%202%(W): 0.06; %195%%232%%202%%246%: 片式厚膜电阻器-0.0625W-15000OHM-+/-1%-0402-BT; %208%%161%%192%%224%%195%%251%%179%%198%: 片式厚膜电阻器; %215%%232%%214%%181%%212%%202%%208%%237%%198%%171%%178%%238%: +/-1%; CODE: 7091372; COMPONENT_HIGH_MAX: 0.4MM; DEVICE: RC_02W1502FT
R70 = R: %182%%238%%182%%168%%185%%166%%194%%202%(W): 0.06; %195%%232%%202%%246%: 片式厚膜电阻器-0.0625W-33000OHM-+/-5%-0402; %208%%161%%192%%224%%195%%251%%179%%198%: 片式厚膜电阻器; %215%%232%%214%%181%%212%%202%%208%%237%%198%%171%%178%%238%: +/-5%; CODE: 7090828; COMPONENT_HIGH_MAX: 0.4MM; DEVICE: RK73B1ELTP333J
LB1 LB7 LB8 LB11 LB14 LB17 LB18 LB20 LB31 LB35 R14 R18 R35-R37 R95 = R: %182%%238%%182%%168%%185%%166%%194%%202%(W): 0.06; %195%%232%%202%%246%: 片式厚膜电阻器-0.0625W-0OHM-< 50MOHM-0402-1A-BT; %208%%161%%192%%224%%195%%251%%179%%198%: 片式厚膜电阻器; %215%%232%%214%%181%%212%%202%%208%%237%%198%%171%%178%%238%: < 50MOHM; CODE: 7090800; DEVICE: RC0402JR_070R
R99 = R: %182%%238%%182%%168%%185%%166%%194%%202%(W): 0.06; %195%%232%%202%%246%: 片式厚膜电阻器-0.0625W-11300OHM-+/-1%-0402; %208%%161%%192%%224%%195%%251%%179%%198%: 片式厚膜电阻器; %215%%232%%214%%181%%212%%202%%208%%237%%198%%171%%178%%238%: +/-1%; CODE: 7090816; COMPONENT_HIGH_MAX: 0.4MM; DEVICE: RC0402FR_0711K3
R101 = R: %182%%238%%182%%168%%185%%166%%194%%202%(W): 0.06; %195%%232%%202%%246%: 片式厚膜电阻器-0.0625W-24000OHM-+/-1%-0402; %208%%161%%192%%224%%195%%251%%179%%198%: 片式厚膜电阻器; %215%%232%%214%%181%%212%%202%%208%%237%%198%%171%%178%%238%: +/-1%; CODE: 7091376; COMPONENT_HIGH_MAX: 0.4MM; DEVICE: RC_02W2402FT
R102 = R: %182%%238%%182%%168%%185%%166%%194%%202%(W): 0.06; %195%%232%%202%%246%: 片式厚膜电阻器-0.0625W-180000OHM-+/-1%-0402; %208%%161%%192%%224%%195%%251%%179%%198%: 片式厚膜电阻器; %215%%232%%214%%181%%212%%202%%208%%237%%198%%171%%178%%238%: +/-1%; CODE: 7090823; COMPONENT_HIGH_MAX: 0.4MM; DEVICE: RC0402FR_07180KL
R104 = R: %182%%238%%182%%168%%185%%166%%194%%202%(W): 0.06; %195%%232%%202%%246%: 片式厚膜电阻器-0.0625W-2200OHM-+/-1%-0402; %208%%161%%192%%224%%195%%251%%179%%198%: 片式厚膜电阻器; %215%%232%%214%%181%%212%%202%%208%%237%%198%%171%%178%%238%: +/-1%; CODE: 7090810; COMPONENT_HIGH_MAX: 0.4MM; DEVICE: RC0402FR_072K2L
R110 = R: %182%%238%%182%%168%%185%%166%%194%%202%(W): 0.06; %195%%232%%202%%246%: 片式厚膜电阻器-0.0625W-75000OHM-+/-1%-0402; %208%%161%%192%%224%%195%%251%%179%%198%: 片式厚膜电阻器; %215%%232%%214%%181%%212%%202%%208%%237%%198%%171%%178%%238%: +/-1%; CODE: 7091008; COMPONENT_HIGH_MAX: 0.4MM; DEVICE: RK73H1ETTD7502F
U11 U13 = SY8032
U14 = MP1484
U15 = SY8009A
C6 = C: %182%%238%%182%%168%%185%%164%%215%%247%%181%%231%%209%%185%(V): 10; %195%%232%%202%%246%: SMD陶瓷电容-10V-220NF-+/-10%-X7R-0603-供电专用-供电专用; %208%%161%%192%%224%%195%%251%%179%%198%: SMD陶瓷电容; CODE: 8070856; COMPONENT_HIGH_MAX: 0.9MM; DEVICE: C0603C224K8RAC7867
Q4 = NPN-BEC: %195%%232%%202%%246%: 三极管-NPN-45V-100MA-225MW-200MV@100MA-SOT-23-180@2MA; %208%%161%%192%%224%%195%%251%%179%%198%: 三极管; CODE: 15050206; COMPONENT_HIGH_MAX: 1.26MM; DEVICE: BC847AE6327
Q13 Q14 = FETP-GSD: %195%%232%%202%%246%: MOSFET-P沟道--8V--3A-50MOHM--8V-SOT23; %208%%161%%192%%224%%195%%251%%179%%198%: MOSFET; CODE: 15060134; COMPONENT_HIGH_MAX: 1.11MM; DEVICE: IRLML6401TR
R98 = R: %182%%238%%182%%168%%185%%166%%194%%202%(W): 0.06; %195%%232%%202%%246%: 片式厚膜电阻器-0.0625W-10000OHM-±5%-0402; %208%%161%%192%%224%%195%%251%%179%%198%: 片式厚膜电阻器; %215%%232%%214%%181%%212%%202%%208%%237%%198%%171%%178%%238%: ±5%; CODE: 7090815; COMPONENT_HIGH_MAX: 0.4MM; DEVICE: RC_02W103JT
R144 = R: %182%%238%%182%%168%%185%%166%%194%%202%(W): 0.06; %195%%232%%202%%246%: 片式厚膜电阻器-0.0625W-4700OHM-+/-5%-0402-BT; %208%%161%%192%%224%%195%%251%%179%%198%: 片式厚膜电阻器; %215%%232%%214%%181%%212%%202%%208%%237%%198%%171%%178%%238%: +/-5%; CODE: 7090793; COMPONENT_HIGH_MAX: 0.4MM; DEVICE: RK73B1ELTP472J
C3 C7 C9-C11 C16 C18 C188 = C: %182%%238%%182%%168%%185%%164%%215%%247%%181%%231%%209%%185%(V): 25; %195%%232%%202%%246%: SMD陶瓷电容-25V-1000NF-+/-10%-X7R-0603; %208%%161%%192%%224%%195%%251%%179%%198%: SMD陶瓷电容; CODE: 8070962; COMPONENT_HIGH_MAX: 0.9MM; DEVICE: CETMK107B7105KA_T
C38 C42 C57 C74 C78 C85 C98 C99 C101 C102 C104 C119 C137 C194 = C: %182%%238%%182%%168%%185%%164%%215%%247%%181%%231%%209%%185%(V): 10; %195%%232%%202%%246%: SMD陶瓷电容-10V-100NF-+/-10%-X5R-0402; %208%%161%%192%%224%%195%%251%%179%%198%: SMD陶瓷电容; CODE: 8070561; COMPONENT_HIGH_MAX: 0.55MM; DEVICE: C0402C104K8PAC_7867
C118 C248 C250 = C: %182%%238%%182%%168%%185%%164%%215%%247%%181%%231%%209%%185%(V): 6.3; %195%%232%%202%%246%: SMD陶瓷电容-6.3V-2200NF-+/-20%-X5R-0402-TS16949; %208%%161%%192%%224%%195%%251%%179%%198%: SMD陶瓷电容; CODE: 8070667; COMPONENT_HIGH_MAX: 0.6MM; DEVICE: GRM155R60J225ME15D
C364 C365 = C: %182%%238%%182%%168%%185%%164%%215%%247%%181%%231%%209%%185%(V): 50; %195%%232%%202%%246%: SMD陶瓷电容-50V-0.03NF-+/-5%-NPO-0402; %208%%161%%192%%224%%195%%251%%179%%198%: SMD陶瓷电容; CODE: 8070604; COMPONENT_HIGH_MAX: 0.55MM; DEVICE: GRM1555C1H300J
R1 = R: %182%%238%%182%%168%%185%%166%%194%%202%(W): 0.1; %195%%232%%202%%246%: 片式厚膜电阻器-0.1W-1000000OHM-±5%-0603; %208%%161%%192%%224%%195%%251%%179%%198%: 片式厚膜电阻器; %215%%232%%214%%181%%212%%202%%208%%237%%198%%171%%178%%238%: ±5%; CODE: 7090263; DEVICE: RC0603JR_071M
R5 R82 = R: %182%%238%%182%%168%%185%%166%%194%%202%(W): 0.06; %195%%232%%202%%246%: 片式厚膜电阻器-0.0625W-75OHM-+/-1%-0402; %208%%161%%192%%224%%195%%251%%179%%198%: 片式厚膜电阻器; %215%%232%%214%%181%%212%%202%%208%%237%%198%%171%%178%%238%: +/-1%; CODE: 7091321; COMPONENT_HIGH_MAX: 0.4MM; DEVICE: RC_02W750FT
R43 R44 R85 R87 = R: %182%%238%%182%%168%%185%%166%%194%%202%(W): 0.06; %195%%232%%202%%246%: 片式厚膜电阻器-0.0625W-270OHM-+/-5%-0402; %208%%161%%192%%224%%195%%251%%179%%198%: 片式厚膜电阻器; %215%%232%%214%%181%%212%%202%%208%%237%%198%%171%%178%%238%: +/-5%; CODE: 7090609; COMPONENT_HIGH_MAX: 0.4MM; DEVICE: RC0402JR_07270R
R56 = R: %182%%238%%182%%168%%185%%166%%194%%202%(W): 0.06; %195%%232%%202%%246%: 片式厚膜电阻器-0.0625W-10000OHM-+/-5%-0402-BT; %208%%161%%192%%224%%195%%251%%179%%198%: 片式厚膜电阻器; %215%%232%%214%%181%%212%%202%%208%%237%%198%%171%%178%%238%: +/-5%; CODE: 7090815; DEVICE: RC_02W103JT
R61 = R: %182%%238%%182%%168%%185%%166%%194%%202%(W): 0.06; %195%%232%%202%%246%: 片式薄膜电阻器-0.0625W-200OHM-+/-0.1%-0402-+/-50PPM/DEGC; %208%%161%%192%%224%%195%%251%%179%%198%: 片式薄膜电阻器; %215%%232%%214%%181%%212%%202%%208%%237%%198%%171%%178%%238%: +/-0.1%; CODE: 7110054; COMPONENT_HIGH_MAX: 0.4MM; DEVICE: RN731ETTP2000B50
R38 R42 R86 R91 R96 R97 = R: %182%%238%%182%%168%%185%%166%%194%%202%(W): 0.06; %195%%232%%202%%246%: 片式厚膜电阻器-0.0625W-10000OHM-+/-5%-0402-BT; %208%%161%%192%%224%%195%%251%%179%%198%: 片式厚膜电阻器; %215%%232%%214%%181%%212%%202%%208%%237%%198%%171%%178%%238%: +/-5%; CODE: 7090815; COMPONENT_HIGH_MAX: 0.4MM; DEVICE: RC_02W103JT
R40 R88 = R: %182%%238%%182%%168%%185%%166%%194%%202%(W): 0.06; %195%%232%%202%%246%: 片式厚膜电阻器-0.0625W-1000OHM-+/-5%-0402-BT; %208%%161%%192%%224%%195%%251%%179%%198%: 片式厚膜电阻器; %215%%232%%214%%181%%212%%202%%208%%237%%198%%171%%178%%238%: +/-5%; CODE: 7090809; COMPONENT_HIGH_MAX: 0.4MM; DEVICE: RC0402JR_071KL
R173 = R: %182%%238%%182%%168%%185%%166%%194%%202%(W): 0.06; %195%%232%%202%%246%: 片式厚膜电阻器-0.0625W-10000OHM-+/-1%-0402-BT; %208%%161%%192%%224%%195%%251%%179%%198%: 片式厚膜电阻器; %215%%232%%214%%181%%212%%202%%208%%237%%198%%171%%178%%238%: +/-1%; CODE: 7090867; COMPONENT_HIGH_MAX: 0.4MM; DEVICE: RK73H1ETTP1002F
X2 = X_B: %195%%232%%202%%246%: 晶体谐振器-24MHZ; %208%%161%%192%%224%%195%%251%%179%%198%: 晶体谐振器; CODE: 12020151; COMPONENT_HIGH_MAX: 1MM; DEVICE: E5SB400000F15D11
C77 C94 C96 C103 C334 = C: %182%%238%%182%%168%%185%%164%%215%%247%%181%%231%%209%%185%(V): 10; %195%%232%%202%%246%: SMD陶瓷电容-10V-1000NF-+/-10%-X5R-0402-BT,TS16949; %208%%161%%192%%224%%195%%251%%179%%198%: SMD陶瓷电容; CODE: 8070612; COMPONENT_HIGH_MAX: 0.55MM; DEVICE: CV05X5R105K10AH
C164 C182 C264 C270 C336 = C: %182%%238%%182%%168%%185%%164%%215%%247%%181%%231%%209%%185%(V): 16; %195%%232%%202%%246%: SMD陶瓷电容-16V-10NF-+/-10%-X7R-0402-BT,TS16949; %208%%161%%192%%224%%195%%251%%179%%198%: SMD陶瓷电容; CODE: 8070449; COMPONENT_HIGH_MAX: 0.55MM; DEVICE: GRM155R71C103KA01D
J7 = SIP2: %195%%232%%202%%246%: 插针-普通方脚插针-2PIN-单排-直式-5.84MM-2.92MM-2.54MM-THT; %208%%161%%192%%224%%195%%251%%179%%198%: 插针; CODE: 14050028; COMPONENT_HIGH_MAX: 8.38MM; DEVICE: TSW_102_23_F_S
LB12 = LB_v2: %195%%232%%202%%246%: EMI磁珠-+/-251000OHM-0.65OHM-0.2A-402; %208%%161%%192%%224%%195%%251%%179%%198%: EMI磁珠; CODE: 10070019; COMPONENT_HIGH_MAX: 0.55MM; DEVICE: BLM15BD102SN1D
R32 = R: %182%%238%%182%%168%%185%%166%%194%%202%(W): 0.06; %195%%232%%202%%246%: 片式厚膜电阻器-0.0625W-12000OHM-+/-1%-0402; %208%%161%%192%%224%%195%%251%%179%%198%: 片式厚膜电阻器; %215%%232%%214%%181%%212%%202%%208%%237%%198%%171%%178%%238%: +/-1%; CODE: 7090817; DEVICE: RC0402FR_0712K
S1 = PSW4_A: CODE: 16100051
S4 = MSW-6A: %195%%232%%202%%246%: 微动开关-SPST-12VDC-0.05A-贴片-0.5MM-5.2*5.2*1.5MM-1,000,000; %208%%161%%192%%224%%195%%251%%179%%198%: 微动开关; COMPONENT_HIGH_MAX: 1.71MM; DEVICE: TMG_533_T_R
C20 = C: %182%%238%%182%%168%%185%%164%%215%%247%%181%%231%%209%%185%(V): 6.3; %195%%232%%202%%246%: SMD陶瓷电容-6.3V-10000NF-+/-10%-X7R-0805; %208%%161%%192%%224%%195%%251%%179%%198%: SMD陶瓷电容; CODE: 8070693; COMPONENT_HIGH_MAX: 1.4MM; DEVICE: GRM21BR70J106KE76L
C97 C100 = C: %182%%238%%182%%168%%185%%164%%215%%247%%181%%231%%209%%185%(V): 6.3; %195%%232%%202%%246%: SMD陶瓷电容-6.3V-470NF-+/-10%-X5R-0402; %208%%161%%192%%224%%195%%251%%179%%198%: SMD陶瓷电容; CODE: 8070625; COMPONENT_HIGH_MAX: 0.55MM; DEVICE: GRM155R60J474KE19D
R45 = R: %182%%238%%182%%168%%185%%166%%194%%202%(W): 0.06; %195%%232%%202%%246%: 片式厚膜电阻器-0.0625W-240OHM-+/- 1%-0402-BT; %208%%161%%192%%224%%195%%251%%179%%198%: 片式厚膜电阻器; %215%%232%%214%%181%%212%%202%%208%%237%%198%%171%%178%%238%: +/- 1%; CODE: 7091782; COMPONENT_HIGH_MAX: 0.4MM; DEVICE: RC0402FR_07240RL
U1 = Hi3798MV100: DEVICE: HI3798MV100_A

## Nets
1V1_CORE: C37.1(A) C51.1(A) C82.2(B) C90.1(A) L3.2(B) LB11.1(A) LB12.2 LB31.1(A) R101.2(B) ; also on sheet 9
1V1_CPU: C28.1 C35.1(A) C41.1(A) C76.2(B) C116.1(A) L2.2(B) R53.2(B) ; also on sheet 9
1V5_DDR3: C20.1(A) C40.1(A) C68.1(A) C84.2(B) C94.1(A) C96.1(A) C97.1(A) C98.1(A) C99.1(A) C100.1(A) C101.1(A) C102.1(A) C103.1(A) C104.1(A) C110.1(A) C137.1(A) L4.2(B) R10.2(B) U1.J6(VDDIO_DDR_8) U1.J7(VDDIO_DDR_1) U1.K6(VDDIO_DDR_5) U1.K7(VDDIO_DDR_2) U1.L6(VDDIO_DDR_7) U1.N6(VDDIO_DDR_9) U1.P6(VDDIO_DDR_4) U1.T6(VDDIO_DDR_12) U1.T9(VDDIO_CK_DDR_1) U1.T10(VDDIO_CK_DDR_2) U1.U6(VDDIO_DDR_10) U1.U7(VDDIO_DDR_25) U1.V5(VDDIO_DDR_21) U1.V6(VDDIO_DDR_13) U1.V7(VDDIO_DDR_6) U1.V8(VDDIO_DDR_26) U1.V9(VDDIO_DDR_23) U1.V11(VDDIO_DDR_24) U1.V12(VDDIO_DDR_3) U1.V13(VDDIO_DDR_11) U1.V14(VDDIO_DDR_22) U1.W4(VDDIO_DDR_20) U1.W5(VDDIO_DDR_19) U1.W6(VDDIO_DDR_18) U1.W7(VDDIO_DDR_17) U1.Y4(VDDIO_DDR_16) U1.Y5(VDDIO_DDR_15) U1.Y6(VDDIO_DDR_14) ; also on sheet 11 12
3V3: C2.1(A) C4.1(A) C25.1(A) C26.1(A) C27.1(A) C39.1(A) C46.1(A) C53.1(A) C67.1(A) C69.1(A) C91.1(A) C114.1(A) L5.2(B) Q13.2(S) R6.1(A) R88.2(B) R105.2(B) U11.4(VIN) U13.4(VIN) U15.4(VIN) ; also on sheet 9 15 17
3V3_MOS: C74.1(A) LB1.2(B) LB7.2(B) LB8.2(B) LB14.1(A) LB17.2(B) LB18.1(A) LB20.1(A) LB35.1(A) Q13.3(D) R42.1(A) R91.2(B) R97.2(B) U1.M19(DVDD3318_NF_2) U1.N19(DVDD3318_NF_1) ; also on sheet 9 13 14 15 17 18 19
5V0: C6.1(A) C58.1 C59.1(A) C111.1(A) C112.1(A) D6.2(A) J1.1(A1) J10.1(A1) Q14.2(S) R4.1(A) R144.1(A) U14.2(IN)
5V0_MOS: Q14.3(D) ; also on sheet 14 16 19
AVDD11_USB3: C16.1(A) C119.1(A) LB11.2(B) U1.R16(DVDD11_USB3) U1.R17(AVDD11_VP_USB3) U1.T17(AVDD11_VPTX0_USB3)
AVDD33_ADAC: C188.1(A) C194.1(A) LB35.2(B) U1.E19(AVDD33_ADAC)
AVDD33_USB2: C3.1(A) LB17.1(A) U1.K19(AVDD33_USB2)
AVDD33_USB3: C18.1(A) LB18.2(B) U1.W17(AVDD33_USB3_1) U1.W18(AVDD33_USB3_2)
GND: C2.2(B) C3.2(B) C4.2(B) C5.2(B) C7.2(B) C8.2(B) C9.2(B) C10.2(B) C11.2(B) C16.2(B) C18.2(B) C20.2(B) C24.2(B) C25.2(B) C26.2(B) C27.2(B) C28.2 C30.2(B) C35.2(B) C37.2(B) C38.2(B) C39.2(B) C40.2(B) C41.2(B) C42.1(A) C43.2(B) C44.2(B) C45.2(B) C46.2(B) C51.2(B) C53.2(B) C57.2(B) C58.2 C59.2(B) C67.2(B) C68.2(B) C69.2(B) C71.2(B) C72.2(B) C74.2(B) C77.2(B) C78.2(B) C85.2(B) C90.2(B) C91.2(B) C94.2(B) C96.2(B) C97.2(B) C98.2(B) C99.2(B) C100.2(B) C101.2(B) C102.2(B) C103.2(B) C104.2(B) C110.2(B) C111.2(B) C112.2(B) C114.2(B) C116.2(B) C118.1(A) C119.2(B) C137.2(B) C164.2(B) C182.2(B) C188.2(B) C194.2(B) C248.2(B) C250.1(A) C251.2(B) C264.2(B) C270.2(B) C281.2(B) C334.2(B) C336.2(B) C364.2(B) C365.2(B) J1.2(A2) J1.3(A3) J3.1 J4.1 J5.1 J7.2(A2) J10.2(A2) J10.3(A3) M20.1(GND0) M20.2(GND1) M20.3(GND2) M20.4(GND3) M20.5(GND4) M20.6(GND5) M20.7(GND6) M20.8(GND7) M21.1(GND0) M21.2(GND1) M21.3(GND2) M21.4(GND3) M21.5(GND4) M21.6(GND5) M21.7(GND6) M21.8(GND7) M22.1(GND0) M22.2(GND1) M22.3(GND2) M22.4(GND3) M22.5(GND4) M22.6(GND5) M22.7(GND6) M22.8(GND7) M23.1(GND0) M23.2(GND1) M23.3(GND2) M23.4(GND3) M23.5(GND4) M23.6(GND5) M23.7(GND6) M23.8(GND7) Q4.2(E) R13.1(A) R32.1(A) R38.1(A) R43.2(B) R44.1(A) R45.2(B) R52.2(B) R56.1(A) R61.1(A) R85.2(B) R86.2(B) R87.1(A) R96.2(B) R99.1(A) R100.2(B) R104.2(B) R173.2(B) S1.1 S1.3 S1.4 S4.3 S4.4 S4.5 S4.6 U1.A3(AVSS_FE_4) U1.A23(AVSS_ADAC_5) U1.B3(AVSS_FE_2) U1.B8(AVSS_USB1_2) U1.B23(AVSS_ADAC_4) U1.C4(AVSS_FE_3) U1.C6(AVSS_USB0) U1.C8(AVSS_USB1_1) U1.C15(AVSS_HDMITX_1) U1.C17(AVSS_HDMITX_2) U1.C21(AVSS_ADAC_2) U1.C22(AVSS_ADAC_3) U1.D4(AVSS_FE_1) U1.D6(AVSS_USB2_3) U1.D14(AVSS_HDMITX_5) U1.D15(AVSS_HDMITX_3) U1.D17(AVSS_HDMITX_4) U1.D20(AVSS_ADAC_1) U1.D21(AVSS_VDAC_1) U1.D22(AVSS_VDAC_5) U1.E16(AVSS_HDMITX_7) U1.E17(AVSS_HDMITX_6) U1.E21(AVSS_VDAC_2) U1.E22(AVSS_VDAC_3) U1.F21(AVSS_VDAC_4) U1.G20(AVSS_VDAC_6) U1.L20(AVSS_USB2_1) U1.L21(AVSS_USB2_2) U11.2(GND) U13.2(GND) U14.4(GND1) U14.9(GND2) U15.2(GND) X2.2(GND1) X2.4(GND2) ; also on sheet 9 10 11 12 13 14 15 16 17 18 19
ADAC_VOUTL: U1.B22(ADAC_VOUTL) ; also on sheet 16
ADAC_VOUTR: U1.A22(ADAC_VOUTR) ; also on sheet 16
CORE_CTRL: R23.2(B) U1.H22(GPIO2_6/I2C2_SCL/PMC_PWM0)
CPU_CTRL: R21.2(B) U1.H23(GPIO2_7/I2C2_SDA/PMC_PWM1)
CVBS: U1.E23(VDAC) ; also on sheet 18
DDR_ADDR0: U1.AC14(DDR3_A0) ; also on sheet 11 12
DDR_ADDR1: U1.Y10(DDR3_A1) ; also on sheet 11 12
DDR_ADDR2: U1.W14(DDR3_A2) ; also on sheet 11 12
DDR_ADDR3: U1.AB14(DDR3_A3) ; also on sheet 11 12
DDR_ADDR4: U1.W10(DDR3_A4) ; also on sheet 11 12
DDR_ADDR5: U1.Y16(DDR3_A5) ; also on sheet 11 12
DDR_ADDR6: U1.AA10(DDR3_A6) ; also on sheet 11 12
DDR_ADDR7: U1.AA16(DDR3_A7) ; also on sheet 11 12
DDR_ADDR8: U1.AB11(DDR3_A8) ; also on sheet 11 12
DDR_ADDR9: U1.AA12(DDR3_A9) ; also on sheet 11 12
DDR_ADDR10: U1.Y8(DDR3_A10) ; also on sheet 11 12
DDR_ADDR11: U1.Y11(DDR3_A11) ; also on sheet 11 12
DDR_ADDR12: U1.AB9(DDR3_A12) ; also on sheet 11 12
DDR_ADDR13: U1.Y15(DDR3_A13) ; also on sheet 11 12
DDR_ADDR14: U1.AA11(DDR3_A14) ; also on sheet 11 12
DDR_ADDR15: U1.W12(DDR3_A15) ; also on sheet 11 12
DDR_BA0: U1.AC15(DDR3_BA0) ; also on sheet 11 12
DDR_BA1: U1.AA9(DDR3_BA1) ; also on sheet 11 12
DDR_BA2: U1.Y12(DDR3_BA2) ; also on sheet 11 12
DDR_CASN: U1.Y14(DDR3_CAS_N) ; also on sheet 11 12
DDR_CKE: R38.2(B) U1.W9(DDR3_CKE) ; also on sheet 11 12
DDR_CLK0N: R35.1(A) ; also on sheet 11
DDR_CLK0P: R18.1(A) ; also on sheet 11
DDR_CLK1N: R37.1(A) ; also on sheet 12
DDR_CLK1P: R36.1(A) ; also on sheet 12
DDR_CSN: U1.AC12(DDR3_CS_N_0) ; also on sheet 11 12
DDR_DM0: U1.K4(DDR3_DM0) ; also on sheet 11
DDR_DM1: U1.L5(DDR3_DM1) ; also on sheet 11
DDR_DM2: U1.AA1(DDR3_DM2) ; also on sheet 12
DDR_DM3: U1.Y2(DDR3_DM3) ; also on sheet 12
DDR_DQ0: U1.H4(DDR3_DQ0) ; also on sheet 11
DDR_DQ1: U1.N1(DDR3_DQ1) ; also on sheet 11
DDR_DQ2: U1.H1(DDR3_DQ2) ; also on sheet 11
DDR_DQ3: U1.P3(DDR3_DQ3) ; also on sheet 11
DDR_DQ4: U1.H5(DDR3_DQ4) ; also on sheet 11
DDR_DQ5: U1.R3(DDR3_DQ5) ; also on sheet 11
DDR_DQ6: U1.H2(DDR3_DQ6) ; also on sheet 11
DDR_DQ7: U1.P2(DDR3_DQ7) ; also on sheet 11
DDR_DQ8: U1.M4(DDR3_DQ8) ; also on sheet 11
DDR_DQ9: U1.K2(DDR3_DQ9) ; also on sheet 11
DDR_DQ10: U1.M5(DDR3_DQ10) ; also on sheet 11
DDR_DQ11: U1.J3(DDR3_DQ11) ; also on sheet 11
DDR_DQ12: U1.N4(DDR3_DQ12) ; also on sheet 11
DDR_DQ13: U1.J4(DDR3_DQ13) ; also on sheet 11
DDR_DQ14: U1.P4(DDR3_DQ14) ; also on sheet 11
DDR_DQ15: U1.J5(DDR3_DQ15) ; also on sheet 11
DDR_DQ16: U1.T5(DDR3_DQ16) ; also on sheet 12
DDR_DQ17: U1.AA5(DDR3_DQ17) ; also on sheet 12
DDR_DQ18: U1.T2(DDR3_DQ18) ; also on sheet 12
DDR_DQ19: U1.AB5(DDR3_DQ19) ; also on sheet 12
DDR_DQ20: U1.R5(DDR3_DQ20) ; also on sheet 12
DDR_DQ21: U1.AC6(DDR3_DQ21) ; also on sheet 12
DDR_DQ22: U1.T3(DDR3_DQ22) ; also on sheet 12
DDR_DQ23: U1.AA6(DDR3_DQ23) ; also on sheet 12
DDR_DQ24: U1.AA4(DDR3_DQ24) ; also on sheet 12
DDR_DQ25: U1.U1(DDR3_DQ25) ; also on sheet 12
DDR_DQ26: U1.AB3(DDR3_DQ26) ; also on sheet 12
DDR_DQ27: U1.U3(DDR3_DQ27) ; also on sheet 12
DDR_DQ28: U1.AC2(DDR3_DQ28) ; also on sheet 12
DDR_DQ29: U1.T4(DDR3_DQ29) ; also on sheet 12
DDR_DQ30: U1.AB2(DDR3_DQ30) ; also on sheet 12
DDR_DQ31: U1.U4(DDR3_DQ31) ; also on sheet 12
DDR_DQS0N: U1.L1(DDR3_DQS0_N) ; also on sheet 11
DDR_DQS0P: U1.L2(DDR3_DQS0_P) ; also on sheet 11
DDR_DQS1N: U1.M3(DDR3_DQS1_N) ; also on sheet 11
DDR_DQS1P: U1.M2(DDR3_DQS1_P) ; also on sheet 11
DDR_DQS2N: U1.V2(DDR3_DQS2_N) ; also on sheet 12
DDR_DQS2P: U1.V3(DDR3_DQS2_P) ; also on sheet 12
DDR_DQS3N: U1.W2(DDR3_DQS3_N) ; also on sheet 12
DDR_DQS3P: U1.W1(DDR3_DQS3_P) ; also on sheet 12
DDR_ODT: U1.AB15(DDR3_ODT_0) ; also on sheet 11 12
DDR_PLL: C11.1(A) C264.1(A) C270.1(A) LB7.1(A) U1.N8(AVDD_DDRPLL1) U1.T12(AVDD_DDRPLL2)
DDR_RASN: U1.AB16(DDR3_RAS_N) ; also on sheet 11 12
DDR_RESETN: U1.AB13(DDR3_RESET_N) ; also on sheet 11 12
DDR_WEN: U1.Y13(DDR3_WE_N) ; also on sheet 11 12
FE_1V1: C248.1(A) U1.G10(AVDD11_FE)
FE_3V3: C7.1(A) LB8.1(A) U1.E5(AVDD33_FE)
HDMI_TX0N: U1.D16(HDMI_TX0N) ; also on sheet 19
HDMI_TX0P: U1.C16(HDMI_TX0P) ; also on sheet 19
HDMI_TX1N: U1.B15(HDMI_TX1N) ; also on sheet 19
HDMI_TX1P: U1.A15(HDMI_TX1P) ; also on sheet 19
HDMI_TX2N: U1.C14(HDMI_TX2N) ; also on sheet 19
HDMI_TX2P: U1.B14(HDMI_TX2P) ; also on sheet 19
HDMI_TX_1V1: C78.1(A) C164.1(A) C251.1(A) C281.1(A) LB12.1 U1.G14(AVCC11_HDMITX_1) U1.G15(AVCC11_HDMITX_2)
HDMI_TX_3V3: C57.1(A) C77.1(A) LB1.1(A) U1.E15(AVCC33_HDMITX)
HDMI_TX_CEC: U1.C18(GPIO4_7/HDMITX_CEC) ; also on sheet 19
HDMI_TX_HOTPLUG: U1.B19(GPIO4_6/HDMITX_HOTPLUG) ; also on sheet 19
HDMI_TX_SCL: U1.D18(GPIO4_5/HDMITX_SCL) ; also on sheet 19
HDMI_TX_SDA: U1.A19(GPIO4_4/HDMITX_SDA) ; also on sheet 19
HDMI_TXCN: U1.B17(HDMI_TXCN) ; also on sheet 19
HDMI_TXCP: U1.A17(HDMI_TXCP) ; also on sheet 19
IR_IN: U1.Y21(GPIO5_1/IR_IN) ; also on sheet 15
LED0_BASE: U1.B2(GPIO2_2/FE_LED_BASE) ; also on sheet 17
LED0_LINK_ACT: U1.B1(GPIO2_1/FE_LED_ACT) ; also on sheet 17
LED_GREEN: U1.AB22(GPIO5_5/LED_DATA) ; also on sheet 15
LED_RED: U1.AC22(GPIO5_6/LED_CLK) ; also on sheet 15
MUTE_CTRL: U1.C19(MUTE_CTRL/GPIO4_3) ; also on sheet 16
NF_ALE_EMMC_PWREN: U1.N20(NF_ALE/SDIO1_CARD_POWER_EN/GPIO0_1) ; also on sheet 13
NF_CLE: U1.N21(NF_CLE/SDIO1_CWPR/GPIO0_2) ; also on sheet 13
NF_CSN0_EMMC_CMD: U1.N22(NF_CSN0/SDIO1_CCMD) ; also on sheet 13
NF_DQ0_EMMC_D0: U1.R23(EBI_DQ0/SDIO1_CDATA0) ; also on sheet 13
NF_DQ1_EMMC_D1: U1.R22(EBI_DQ1/SDIO1_CDATA1) ; also on sheet 13
NF_DQ2_EMMC_D2: U1.R21(EBI_DQ2/SDIO1_CDATA2) ; also on sheet 13
NF_DQ3_EMMC_D3: U1.T21(EBI_DQ3/SDIO1_CDATA3) ; also on sheet 13
NF_DQ4_EMMC_D4: U1.T20(EBI_DQ4/SDIO1_CDATA4) ; also on sheet 13
NF_DQ5_EMMC_D5: U1.U22(EBI_DQ5/SDIO1_CDATA5) ; also on sheet 13
NF_DQ6_EMMC_D6: U1.U23(EBI_DQ6/SDIO1_CDATA6) ; also on sheet 13
NF_DQ7_EMMC_D7_BOOT_SEL0: R86.1(A) U1.U21(EBI_DQ7/SDIO1_CDATA7/BOOT_SEL0) ; also on sheet 13
NF_RDY0_EMMC_RST: U1.M21(NF_RDY0/SDIO1_RST) ; also on sheet 13
NF_REN_EMMC_CLK: R82.1(A) ; also on sheet 13
NF_WEN_EMMC_DET: R56.2(B) U1.P21(NF_WEN/SDIO1_CARD_DETECT/GPIO0_0) ; also on sheet 13
POWER_STB: U1.AA21(GPIO5_2/LED_CSN0) ; also on sheet 15
PWR_OFF/ON: R96.1(A) R97.1(A) U1.J23(JTAG_TDI/GPIO0_7)
RECOVERY: C42.2(B) R42.2(B) S1.2 U1.J22(JTAG_TDO/GPIO2_0)
RX+_PHY0: U1.D5(FE_RXP) ; also on sheet 17
RX-_PHY0: U1.C5(FE_RXN) ; also on sheet 17
SDIO0_CARD_DETECT: U1.F1(SDIO0_CARD_DETECT/GPIO3_6) ; also on sheet 15
SDIO0_CCLK_OUT: R5.1(A) ; also on sheet 15
SDIO0_CCMD: U1.E2(SDIO0_CCMD/GPIO3_3) ; also on sheet 15
SDIO0_CDATA0: U1.D3(SDIO0_CDATA0/GPIO3_1) ; also on sheet 15
SDIO0_CDATA1: U1.C2(SDIO0_CDATA1/GPIO3_0) ; also on sheet 15
SDIO0_CDATA2: U1.F2(SDIO0_CDATA2/GPIO3_5) ; also on sheet 15
SDIO0_CDATA3: U1.E1(SDIO0_CDATA3/GPIO3_4) ; also on sheet 15
SDIO0_CWPR: U1.C1(SDIO0_CWPR/GPIO2_3) ; also on sheet 15
SDIO0_PWREN: U1.F3(SDIO0_CARD_POWER_EN/GPIO3_7) ; also on sheet 15
SDIO_3318: C118.2(B) U1.G5(CAPACITOR_LDO) ; also on sheet 15
SPDIF_OUT_BOOT_SEL1: R91.1(A) U1.A20(SPDIF_OUT/GPIO4_2/BOOT_SEL1) ; also on sheet 16
STANDBY_PWROFF: R48.1(A) R68.1(A) R73.1(A) R88.1(A) R98.1(A) U1.AB23(GPIO5_0/STANDBY_PWROFF)
TX+_PHY0: U1.B4(FE_TXP) ; also on sheet 17
TX-_PHY0: U1.A4(FE_TXN) ; also on sheet 17
UART0_RXD: U1.AA22(UART0_RXD/UART1_RXD) ; also on sheet 17
UART0_TXD: U1.AA23(UART0_TXD/UART1_TXD) ; also on sheet 17
USB0_DM: U1.A6(USB0_DM) ; also on sheet 14
USB0_DP: U1.B6(USB0_DP) ; also on sheet 14
USB01_1V1: C334.1(A) C336.1(A) LB31.2(B) U1.G11(AVCC11_USB01)
USB01_3V3: C10.1(A) C182.1(A) LB20.2(B) U1.D7(AVDD33_USB01)
USB1_DM: U1.B7(USB1_DM) ; also on sheet 14
USB1_DP: U1.C7(USB1_DP) ; also on sheet 14
USB2_DM: U1.L22(USB2_DM) ; also on sheet 14
USB2_DP: U1.L23(USB2_DP) ; also on sheet 14
USB3_DM: U1.AC18(USB3_DM) ; also on sheet 14
USB3_DP: U1.AB18(USB3_DP) ; also on sheet 14
USB3_RXN: U1.AB20(USB3_RXN) ; also on sheet 14
USB3_RXP: U1.AC20(USB3_RXP) ; also on sheet 14
USB3_TXN: U1.AA19(USB3_TXN) ; also on sheet 14
USB3_TXP: U1.Y19(USB3_TXP) ; also on sheet 14
USB_BOOT: C38.1(A) J7.1(A1) R40.1(A) S4.1 S4.2
VDAC_3V3: C9.1(A) C85.1(A) LB14.2(B) U1.E20(AVDD33_VDAC_1) U1.F19(AVDD33_VDAC_2) U1.G19(AVDD33_VDAC_3)
XIN: C364.1(A) R1.2(B) U1.W23(XIN) X2.1
XOUT: R1.1(A) R14.1(A) U1.W22(XOUT)
N14494: R32.2(B) U1.F20(VDAC_IREF)
N14528: C250.2(B) U1.G17(ADAC_VREFDAC)
N14532: R44.2(B) R87.2(B) U1.D8(USB01_REXT)
N14634: R40.2(B) U1.H21(USB_BOOT/GPIO2_5)
N15670: R61.2(B) U1.Y17(USB3_REXT)
N15736: C365.1(A) R14.2(B) X2.3
N15778: R173.1(A) U1.E6(FE_REXT)
N15786: R5.2(B) U1.E3(SDIO0_CCLK_OUT/GPIO3_2)
N16350: Q4.1(B) R98.2(B)
N16386: C6.2(B) Q13.1(G) Q14.1(G) R118.1(A)
N16400: Q4.3(C) R118.2(B) R144.2(B)
N17516: C30.1(A) R6.2(B) R48.2(B) U15.1(EN)
N17644: C65.2(B) L5.1(A) U14.3(SW)
N17654: C65.1(A) R95.2(B)
N17658: C44.1(A) U14.8(SS)
N17664: C82.1(A) R13.2(B) R101.1(A) R110.1(A) U13.6(FB)
N17684: C5.1(A) R68.2(B) U13.1(EN)
N17722: L4.1(A) U15.3(LX)
N17726: C84.1(A) R10.1(A) R52.1(A) U15.5(FB)
N17766: L3.1(A) U13.3(LX)
N17770: R102.1(A) R110.2(B)
N17774: C45.1(A) C72.1(A) R23.1(A) R102.2(B)
N17786: R7.1(A) R70.2(B)
N17790: L2.1(A) U11.3(LX)
N17794: C76.1(A) R53.1(A) R70.1(A) R99.2(B) U11.6(FB)
N17814: C43.1(A) C71.1(A) R7.2(B) R21.1(A)
N17826: R4.2(B) U14.7(EN)
N17832: C24.1(A) C83.1(A) U14.6(COMP/NC)
N17842: C83.2(B) R104.1(A)
N17846: D6.1(K) R95.1(A) U14.1(BS)
N17852: R100.1(A) R105.1(A) U14.5(FB)
N17860: C8.1(A) R73.2(B) U11.1(EN)
N3731011: R43.1(A) R85.1(A) U1.L19(USB2_REXT)
N16849537: R37.2(B) U1.AB7(DDR3_CLK1_N)
N16849539: R36.2(B) U1.AA7(DDR3_CLK1_P)
N16849541: R35.2(B) U1.AB8(DDR3_CLK0_N)
N16849543: R18.2(B) U1.AC8(DDR3_CLK0_P)
N16851079: R45.1(A) U1.W16(DDR3_ZQ)
N17000733: R82.2(B) U1.N23(NF_REN/SDIO1_CCLK_OUT)

Not connected (* = marked no-connect by the designer): ID1 1*; ID2 1*; ID3 1*; ID4 1*; ID5 1*; ID6 1*; M20 9(HOLE)*; M21 9(HOLE)*; M22 9(HOLE)*; M23 9(HOLE)*; U1 A8(GPIO6_7/I2S0_DIN0) A9(GPIO6_5/I2S0_DOUT0) A11(GPIO6_1/SPI_CSN1) A12(GPIO4_1/I2C1_SCL/UART2_TXD/SPI_SDI) B9(GPIO6_6/I2S0_MCLK) B11(GPIO6_0/I2C1_SDA/UART2_RTSN/SPI_CSN0) B12(GPIO4_0/UART2_RXD/SPI_SDO) C9(GPIO6_4/I2S0_WS) C10(GPIO6_3/I2S0_BCLK) C11(GPIO6_2/SLIC_RST) C12(GPIO0_3/UART2_CTSN/SPI_SCLK) G21(JTAG_SEL)* J21(JTAG_TCK/GPIO0_6)* K20(JTAG_TRSTN/GPIO0_5)* K21(JTAG_TMS/GPIO0_4)* Y22(FUNC_SEL)*; U11 5(PG)*; U13 5(PG)*

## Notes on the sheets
sheet 1
- PAGE1
- Title Page
- PAGE2
- Power Tree
- PAGE3
- Block Diagram
- PAGE4
- Power on board
- PAGE5
- Power Ctrl
- PAGE6
- Unit 1 of Hi3798M(NAND/USB3.0/IR/SDIO/XTAL/FE)
- PAGE7
- Unit 2 of Hi3798M(JTAG/USB2.0/HDMI TX/DAC/I2S/SPI/UART)
- PAGE8
- Unit 3 of Hi3798M(DDR3)
- PAGE9
- Unit 4 of Hi3798M(POWER)
- PAGE10
- Unit 5 of Hi3798M(VSS)
- Hi3798MDMO1B
- PAGE11
- DDRA
- PAGE12
- DDRB
- PAGE13
- NAND FLASH/EMMC
- VER_E_V1.0.0.0
- PAGE14
- USB2.0/USB3.0/WIFI
- PAGE15
- SD CARD/IR
- PAGE16
- Audio Output
- PAGE17
- FE PHY/UART
- PAGE18
- VDAC OUTPUT
- Hi3798MV100 DEMO Board
- PAGE19
- HDMI TX
- 2 layers PCB with 2 DDR3 16bit
- Board Size:151mm x 97mm x 1.6mm
sheet 2
- Power Tree
- 5V0_MOS
- PMOS
- 1000mA
- AUDIO AMP
- HDMI
- SPDIF
- 5V
- 5V_VBUS
- USB x 3
- SW x 3
- 3V3
- MAX 2600mA
- 20mA
- 3V3 Standby
- DCDC
- IR & LED
- 3V3_MOS
- 170mA
- CHIP
- I/O
- PMOS
- USB
- SD CARD
- VDAC
- NAND FLASH/eMMC
- ADAC
- FE
- HDMI
- 1V1_CORE
- PLL
- DCDC
- 612mA(MAX 2300mA)
- CORE
- USB
- VDAC
- 1V1_CPU
- 303mA(MAX 2560mA)
- CPU
- HDMI
- DCDC
- FE
- PLL
- 1V5_DDR3
- DCDC
- 421mA(MAX 1000mA)
- DDR PHY
- DDR
sheet 3
- Block Diagram
- 5V0
- KEY
- ETH
- HDMI
- L/R/CVBS
- SPDIF
- COAXIL
- USB2.0
- DDRA
- USB2.0
- Hi3798MV100
- DDRB
- USB3.0
- SD CARD
- LED
- IR/LED/KEY
- IR/LED/KEY
sheet 4
- 5V PLUG-IN
- CPU POWER
- Vcpu=0.92V-1.5V
- 3A
- 1%
- 1%
- 1%
- 1%
- 1%
- 3.3V POWER
- MP1484 3A
- 3A
- CORE POWER
- 0.925V
- 1%
- 1%
- Vcore=0.9V-1.32V
- 3A
- ETA1486 4A
- VOUT=0.923*(1+26.1K/10K)=3.33V
- 1%
- C44=100nF;C65=10nF;R104=5.6K;C83=3.3nF;C24=NC
- R105=26.1K;R100=10K
- MP1484 3A
- 1%
- 1%
- VOUT=0.925*(1+26.1K/10K)=3.34V
- 1%
- 1%
- C44=100nF;C65=10nF;R104=5.6K;C83=3.3nF;C24=NC;R105=26.1K;R100=10K
- DDR POWER
- VOUT=0.6*(1+150K/100K)=1.5V
- 2A
- 1%
- 1%
sheet 5
- Power Ctrl
- STANDBY_PWROFF
- 0
- Power Off
- 1
- Power On
sheet 6
- Unit 1 of Hi3798MV100(NAND/USB3.0/IR/SDIO/XTAL/FE)
- 1%
- 2 Layers
- R82=33ohm
- Close to Hi3798M
- 1%
- 135ohm
- 1%
- 2 Layers
- R5=75ohm
- Close to Hi3798M
- BOOT DEVICE SEL
- BOOT_SEL[1:0]
- BOOT_SEL1
- PD
- 11:eMMC
- 10:NAND Flash
- System Oscillator
- BOOT_SEL0
- PU
- 01:fSD/tSD
- PD
- PU
- ** FE PHY Design guideline **
- A.routing
- 1.Route as 100 Ohm differential impedance.
- 2.Differential pairs should be routed on TOP layer only.
- 3.Differential pairs should be separated from other traces by GND .
- B.trace length
- 1.The length for the differential pairs should be less than 5 inches.
- 2.Match trace length of RX and TX differential pairs, 10 mils max within a pair.
- C.component selection
- 1.REXT resistor should be 10K ohm +/-1%.
- 2.ESD components are suggested for ports protection,
- Put between Hi3798MV100 and transformer.
sheet 7
- Unit 2 of Hi3798MV100(JTAG/USB2.0/HDMI TX/DAC/I2S/SPI/UART)
- ** Audio & Video Design guideline **
- A.VIDEO
- 1%
- 1.VIDEO REXT resistor should be 12K +/-1% precision.
- 2.REXT/COMP should be traced as short as possible,
- and isolated from all other traces.
- B.AUDIO
- 1.VREF should be traced as short as possible,
- and isolated from all other traces.
- NOTE:EMI-1000ohm or 600ohm@100MHz
- R96=NC,R97=10k:power up-->start
- R96=10k,R97=NC:power up-->pull key-->start
- 135ohm
- 1%
- USB0:usb_boot/adb
- ** USB Design guideline **
- A.routing
- 1.Route as 90 Ohm differential impedance.
- 2.Differential pairs should be routed on TOP layer only.
- 3.Differential pairs should be separated from other traces by GND .
- B.trace length
- 1.The length for the differential pairs should be less than 5 inches.
- 2.Match trace length of DP and DM differential pairs, 10 mils max within a pair.
- C.component selection
- 1.USB2.0 REXT resistor should be 135 ohm +/-1% and USB3.0 200 ohm +/-1%.
- 2.ESD components are suggested for ports protection.
- 3.Equivalent capacitance of ESD component should be < 1.5pF.
sheet 8
- Unit 3 of Hi3798MV100(DDR)
- 1%
- Close to Hi3798M
- ** DDR Design guideline **
- A.general suggestion
- 1.Hi3798MV100 supports up to 2GB DDR3.
- 2.DDR chip and DDR controller both need at least one 10uF decoupling ceramic capacitor.
- 3.The ciruit of DDR_VREF_CA and DDR_VREF_DQ must be independent
- 4. 3V3 DDRPLL is needed.
- B.Layout suggestion
- 1. Please copy hisilicon demo board completely
